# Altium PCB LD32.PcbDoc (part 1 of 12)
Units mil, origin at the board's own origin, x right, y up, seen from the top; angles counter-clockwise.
Board outline 7007.87 x 4368.85 mil, 12 copper layers (Top Layer, Int1 (GND), Int2 (AVDD), Int3 (DVDD), Int4 (GND), Int5 (ST), Int6 (SB), Int8 (AGND), Int7 (AVCC), Int9 (VCCA), Int10 (GND), Bottom Layer), stack 60.136 mil thick; 1165 components, 667 nets, 3910 pads, 2570 vias.
Unrouted connection lines stored in the file: 14.
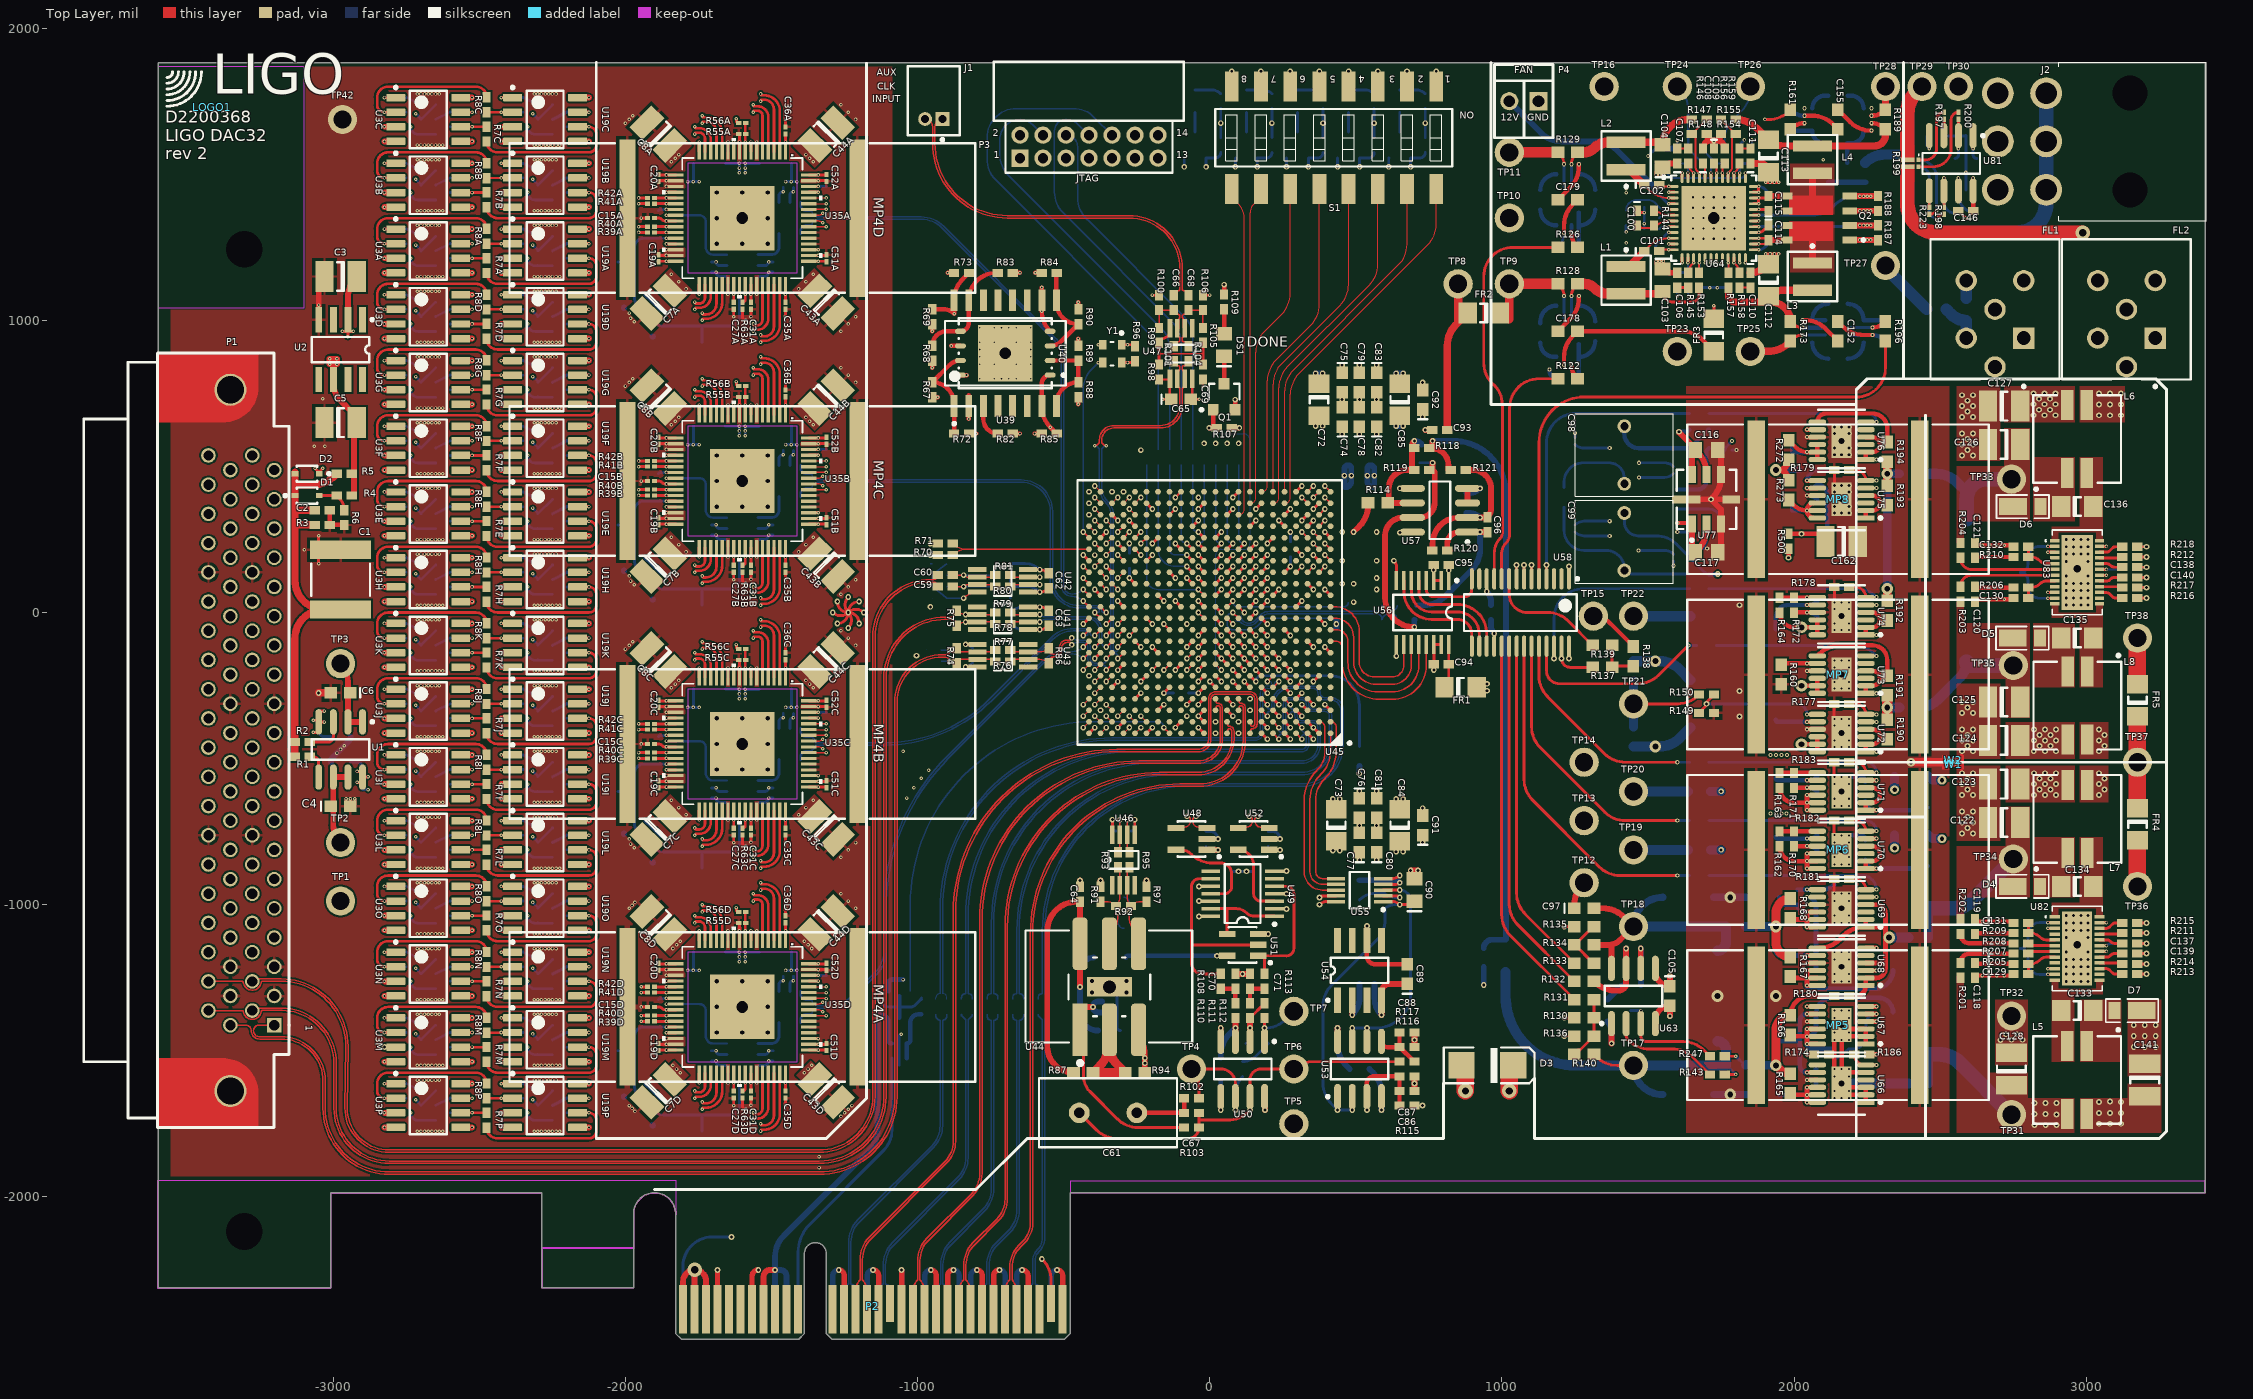
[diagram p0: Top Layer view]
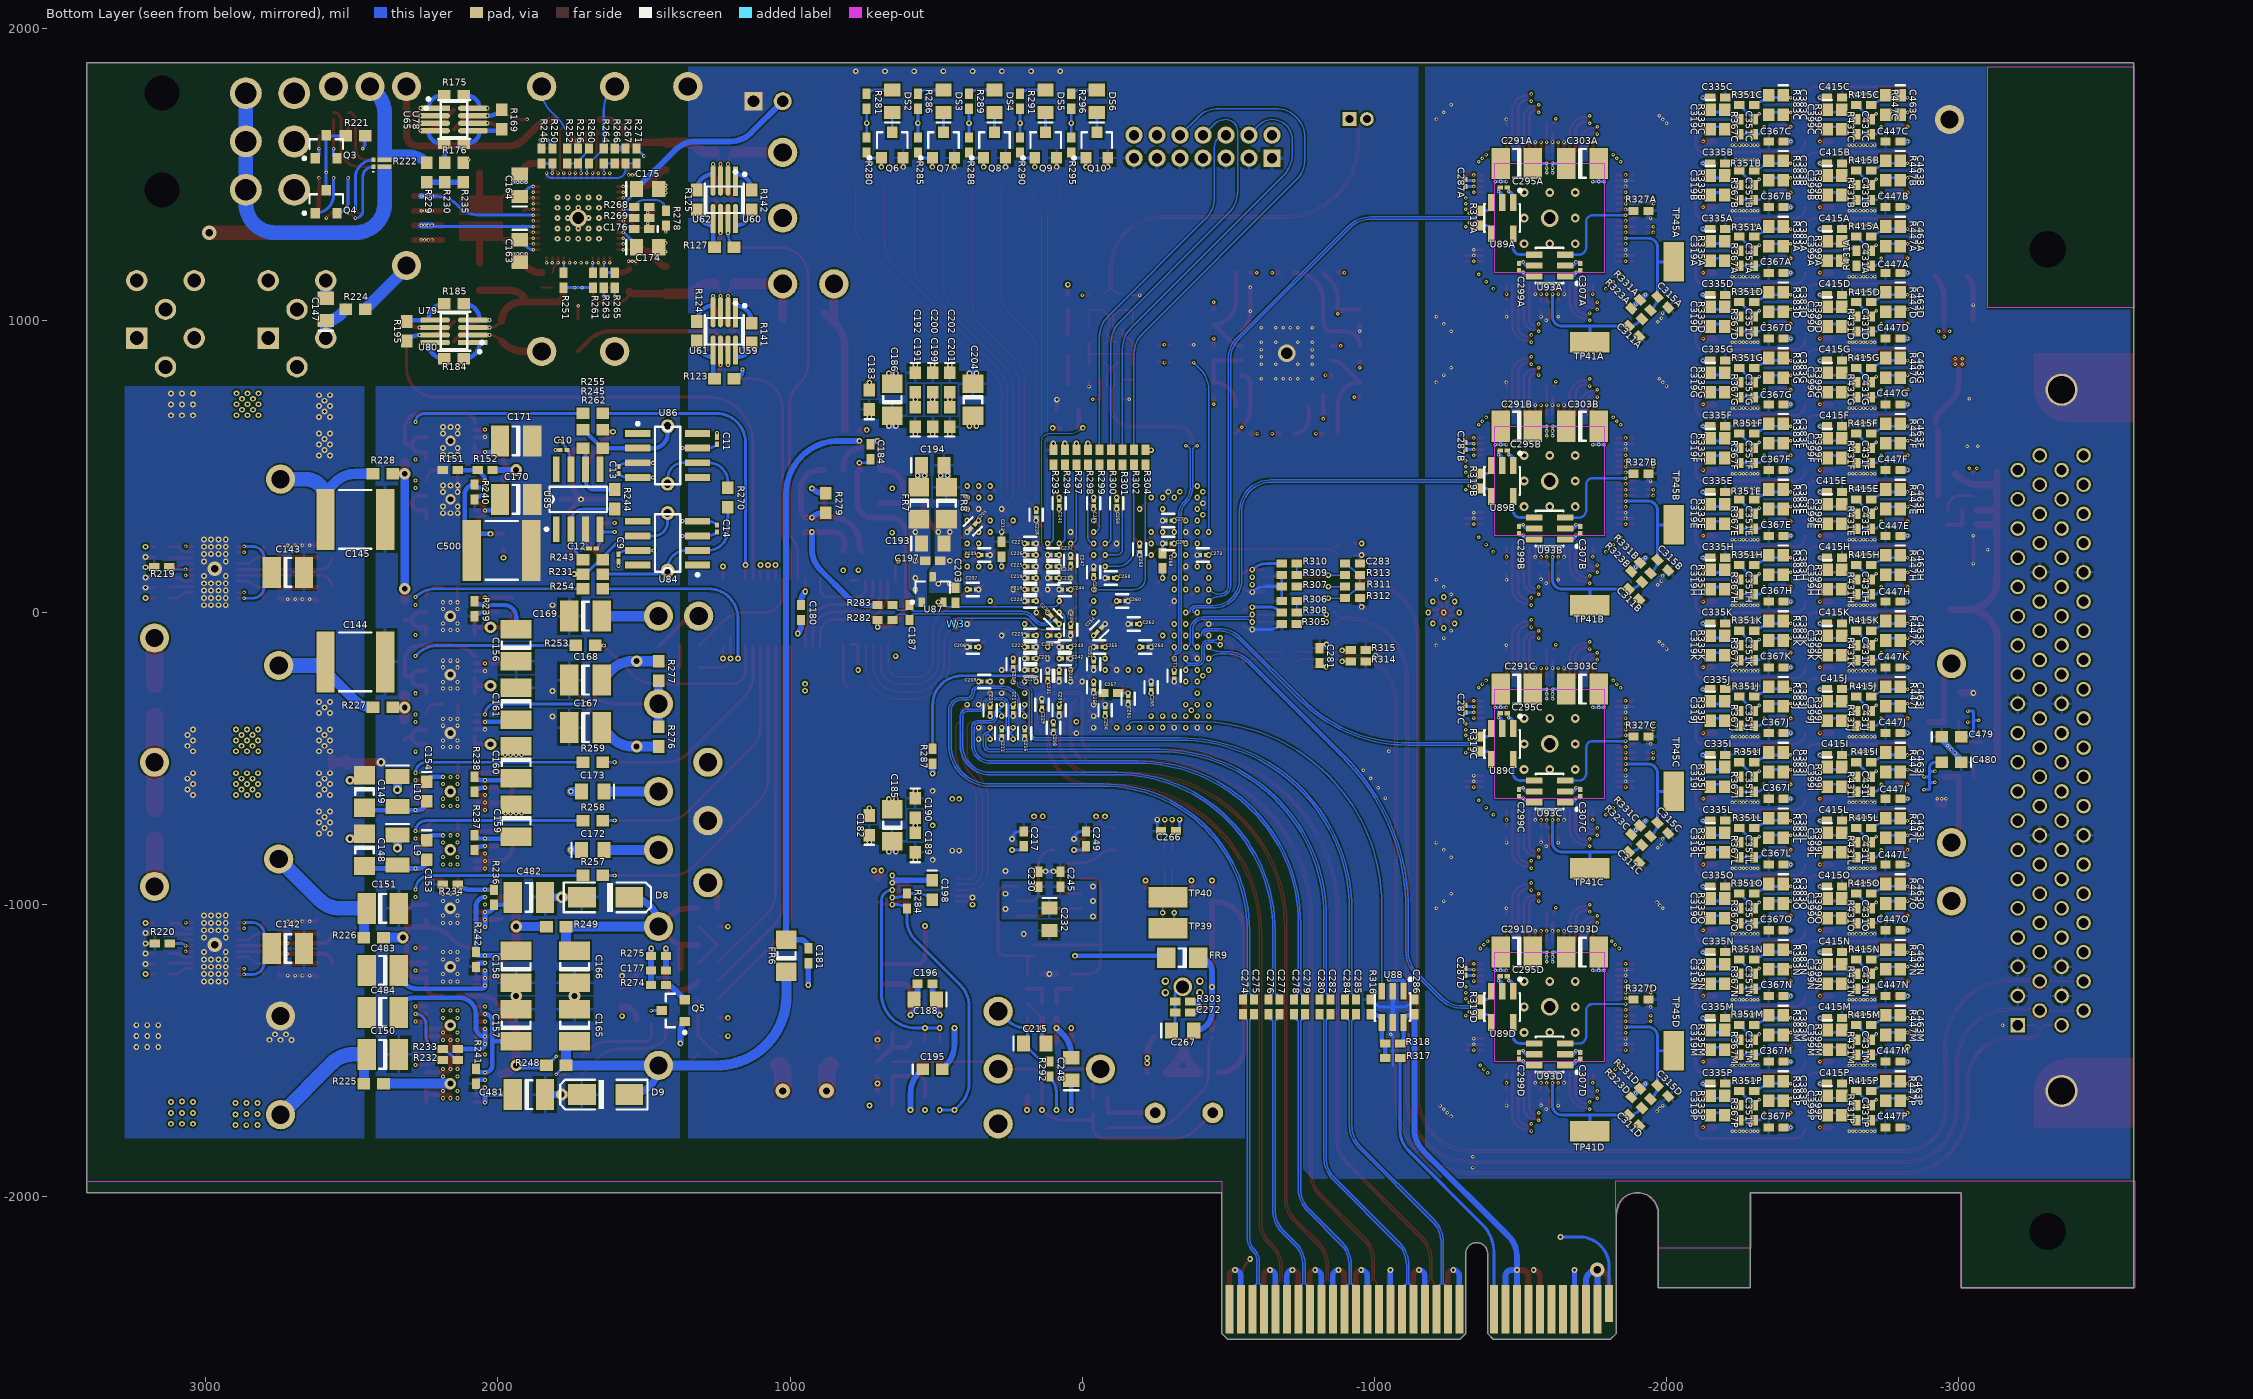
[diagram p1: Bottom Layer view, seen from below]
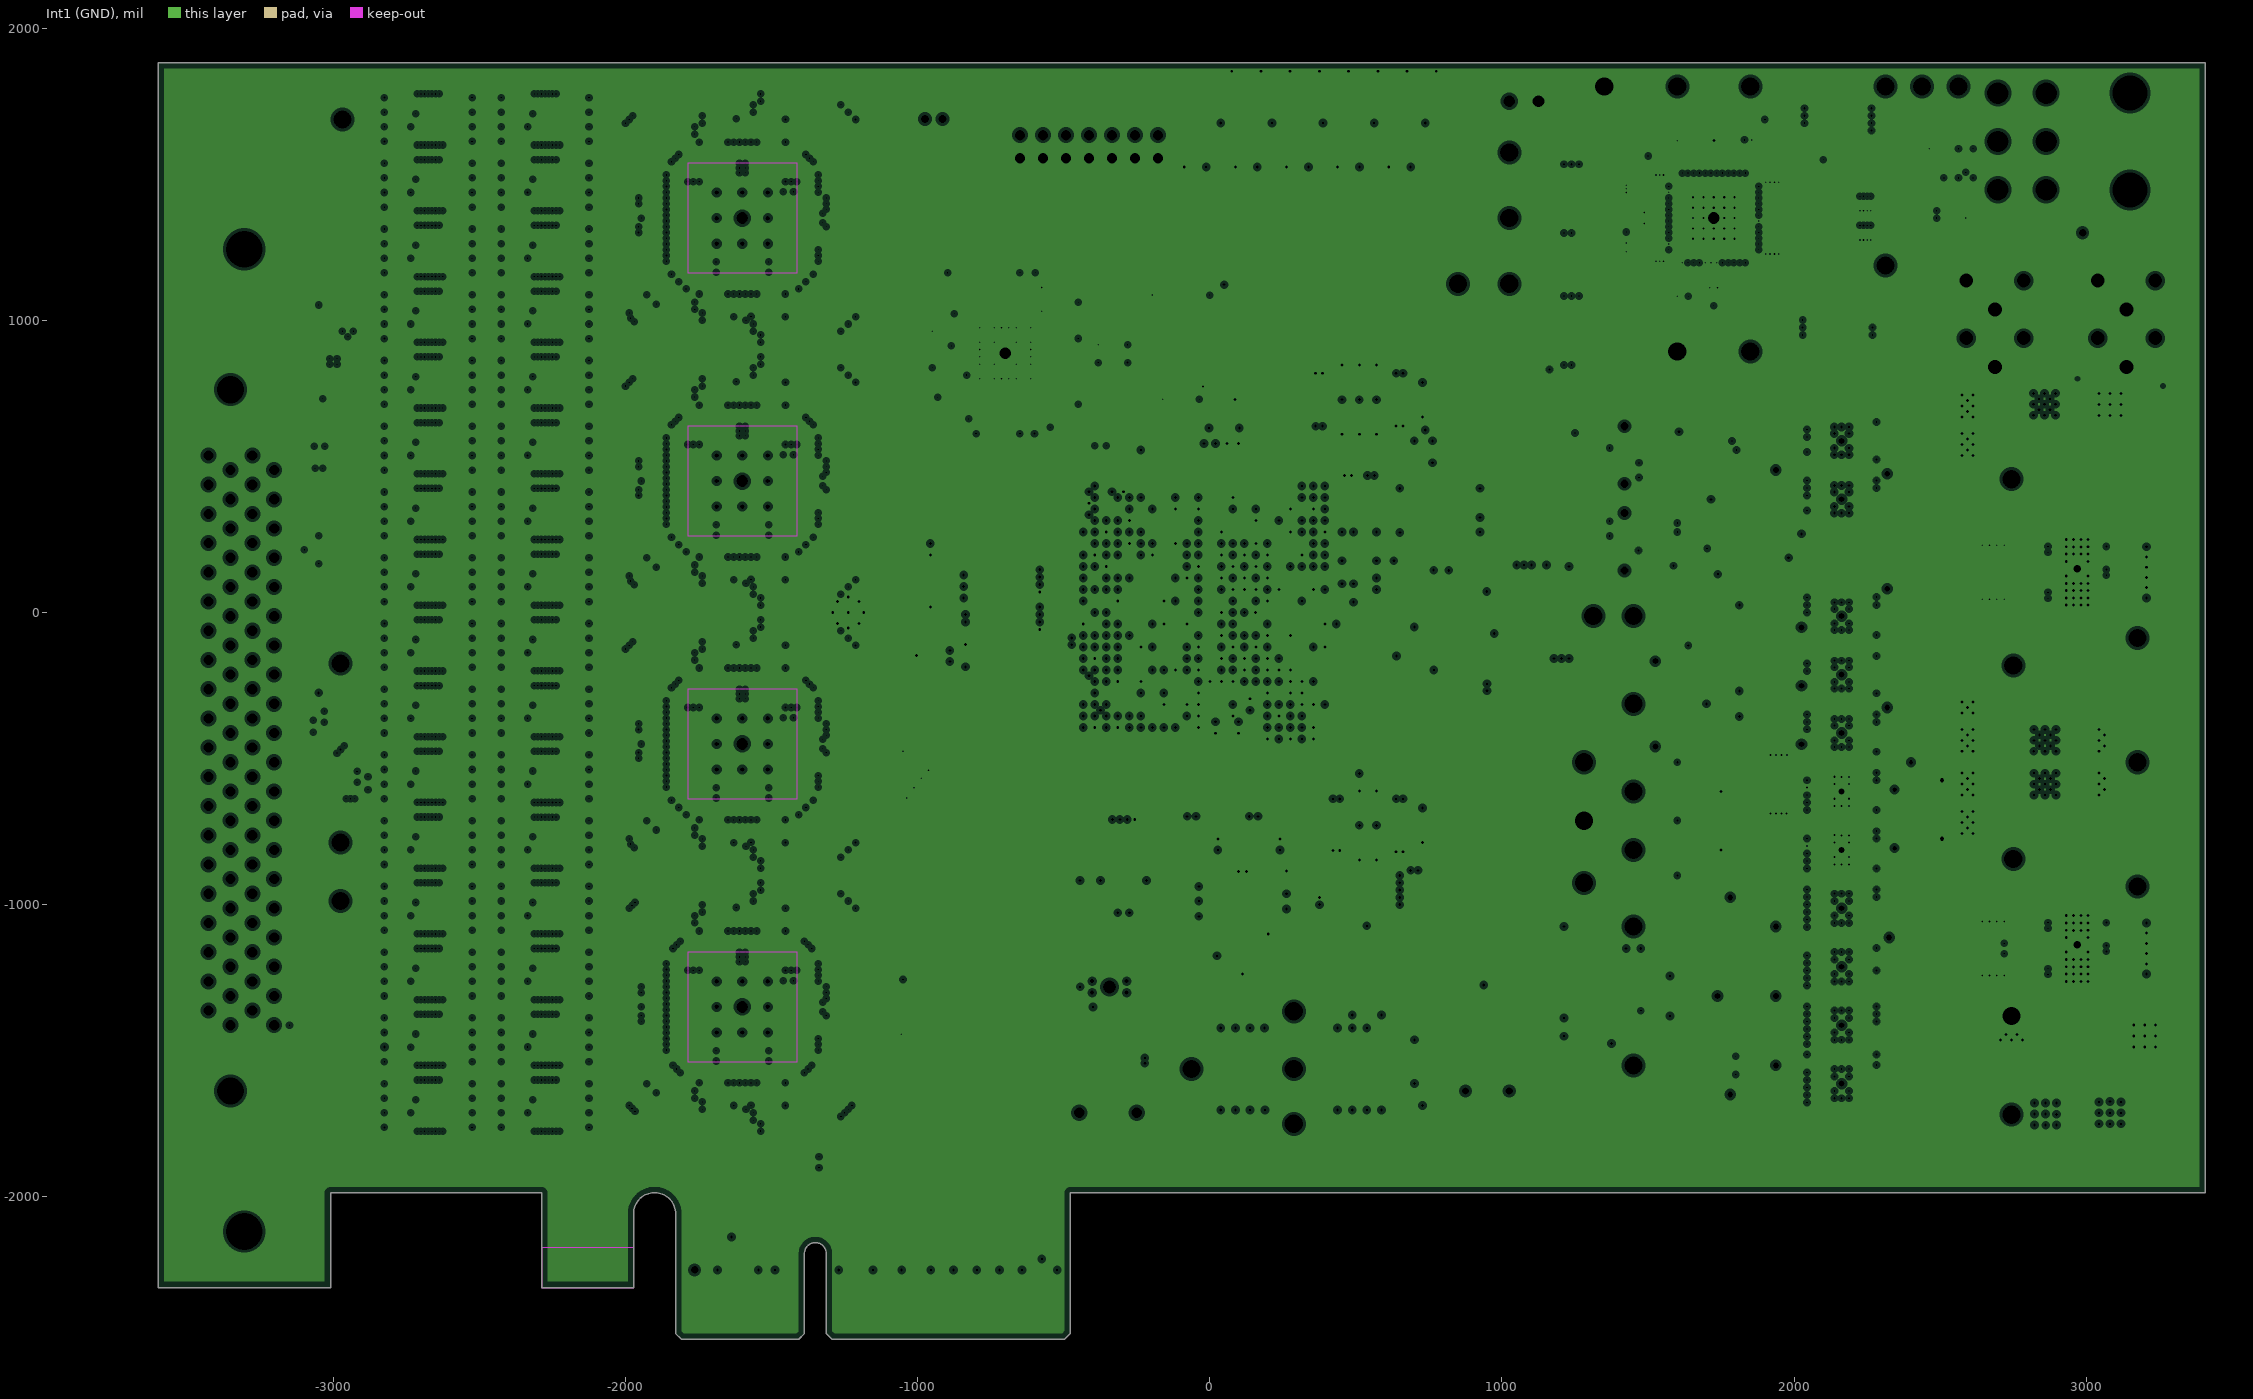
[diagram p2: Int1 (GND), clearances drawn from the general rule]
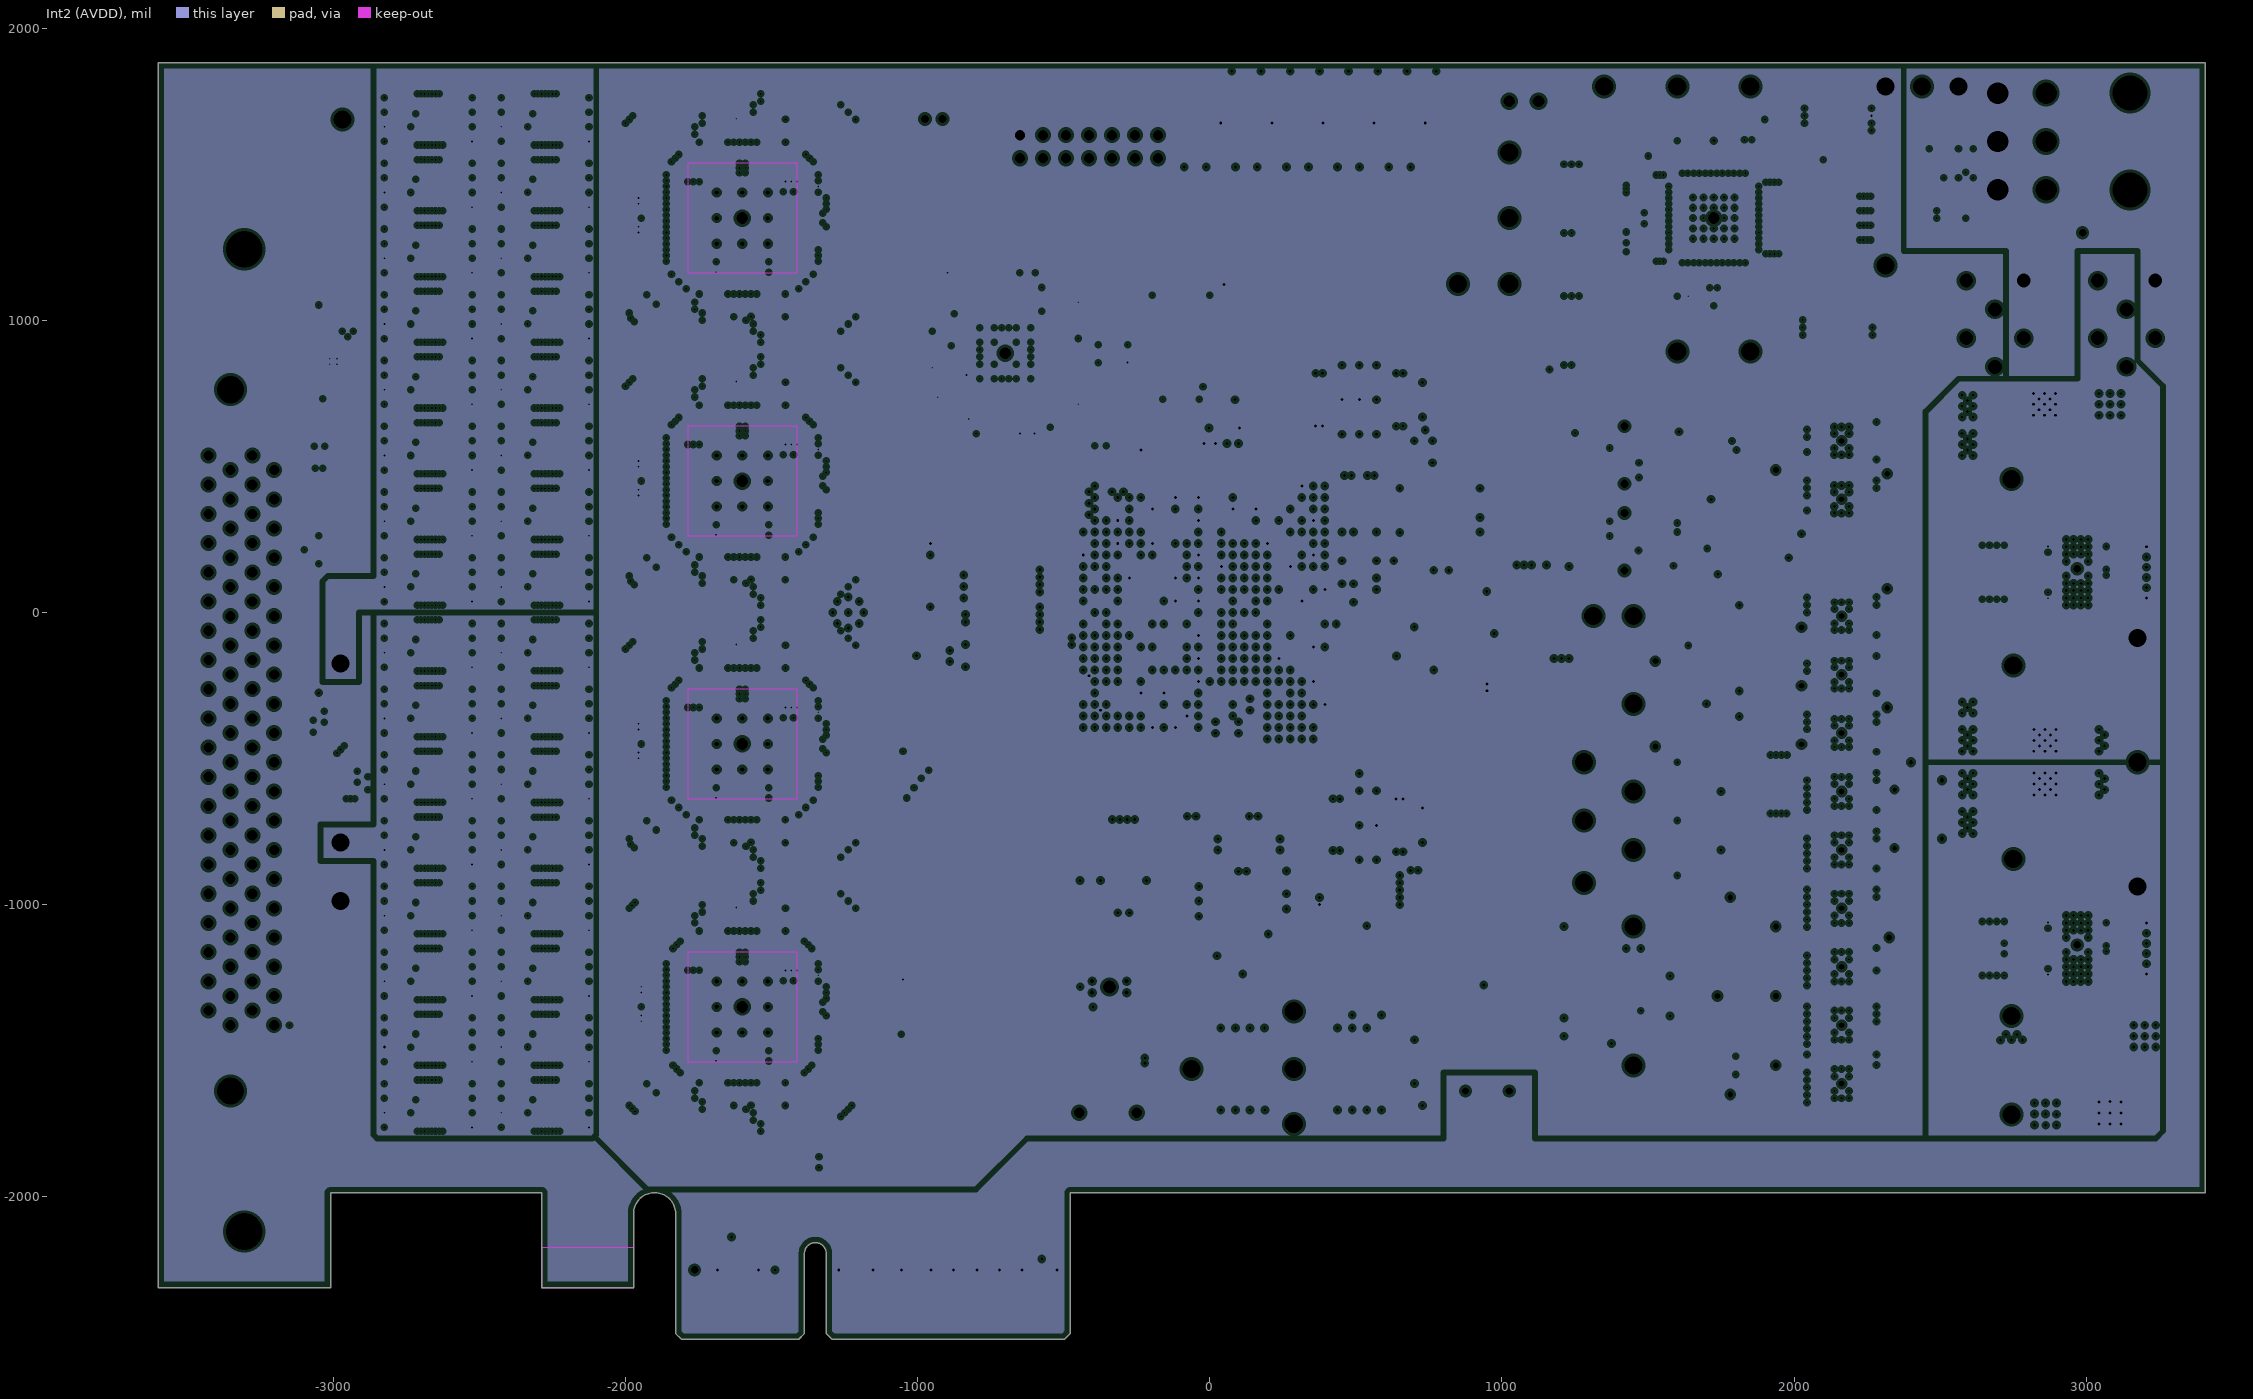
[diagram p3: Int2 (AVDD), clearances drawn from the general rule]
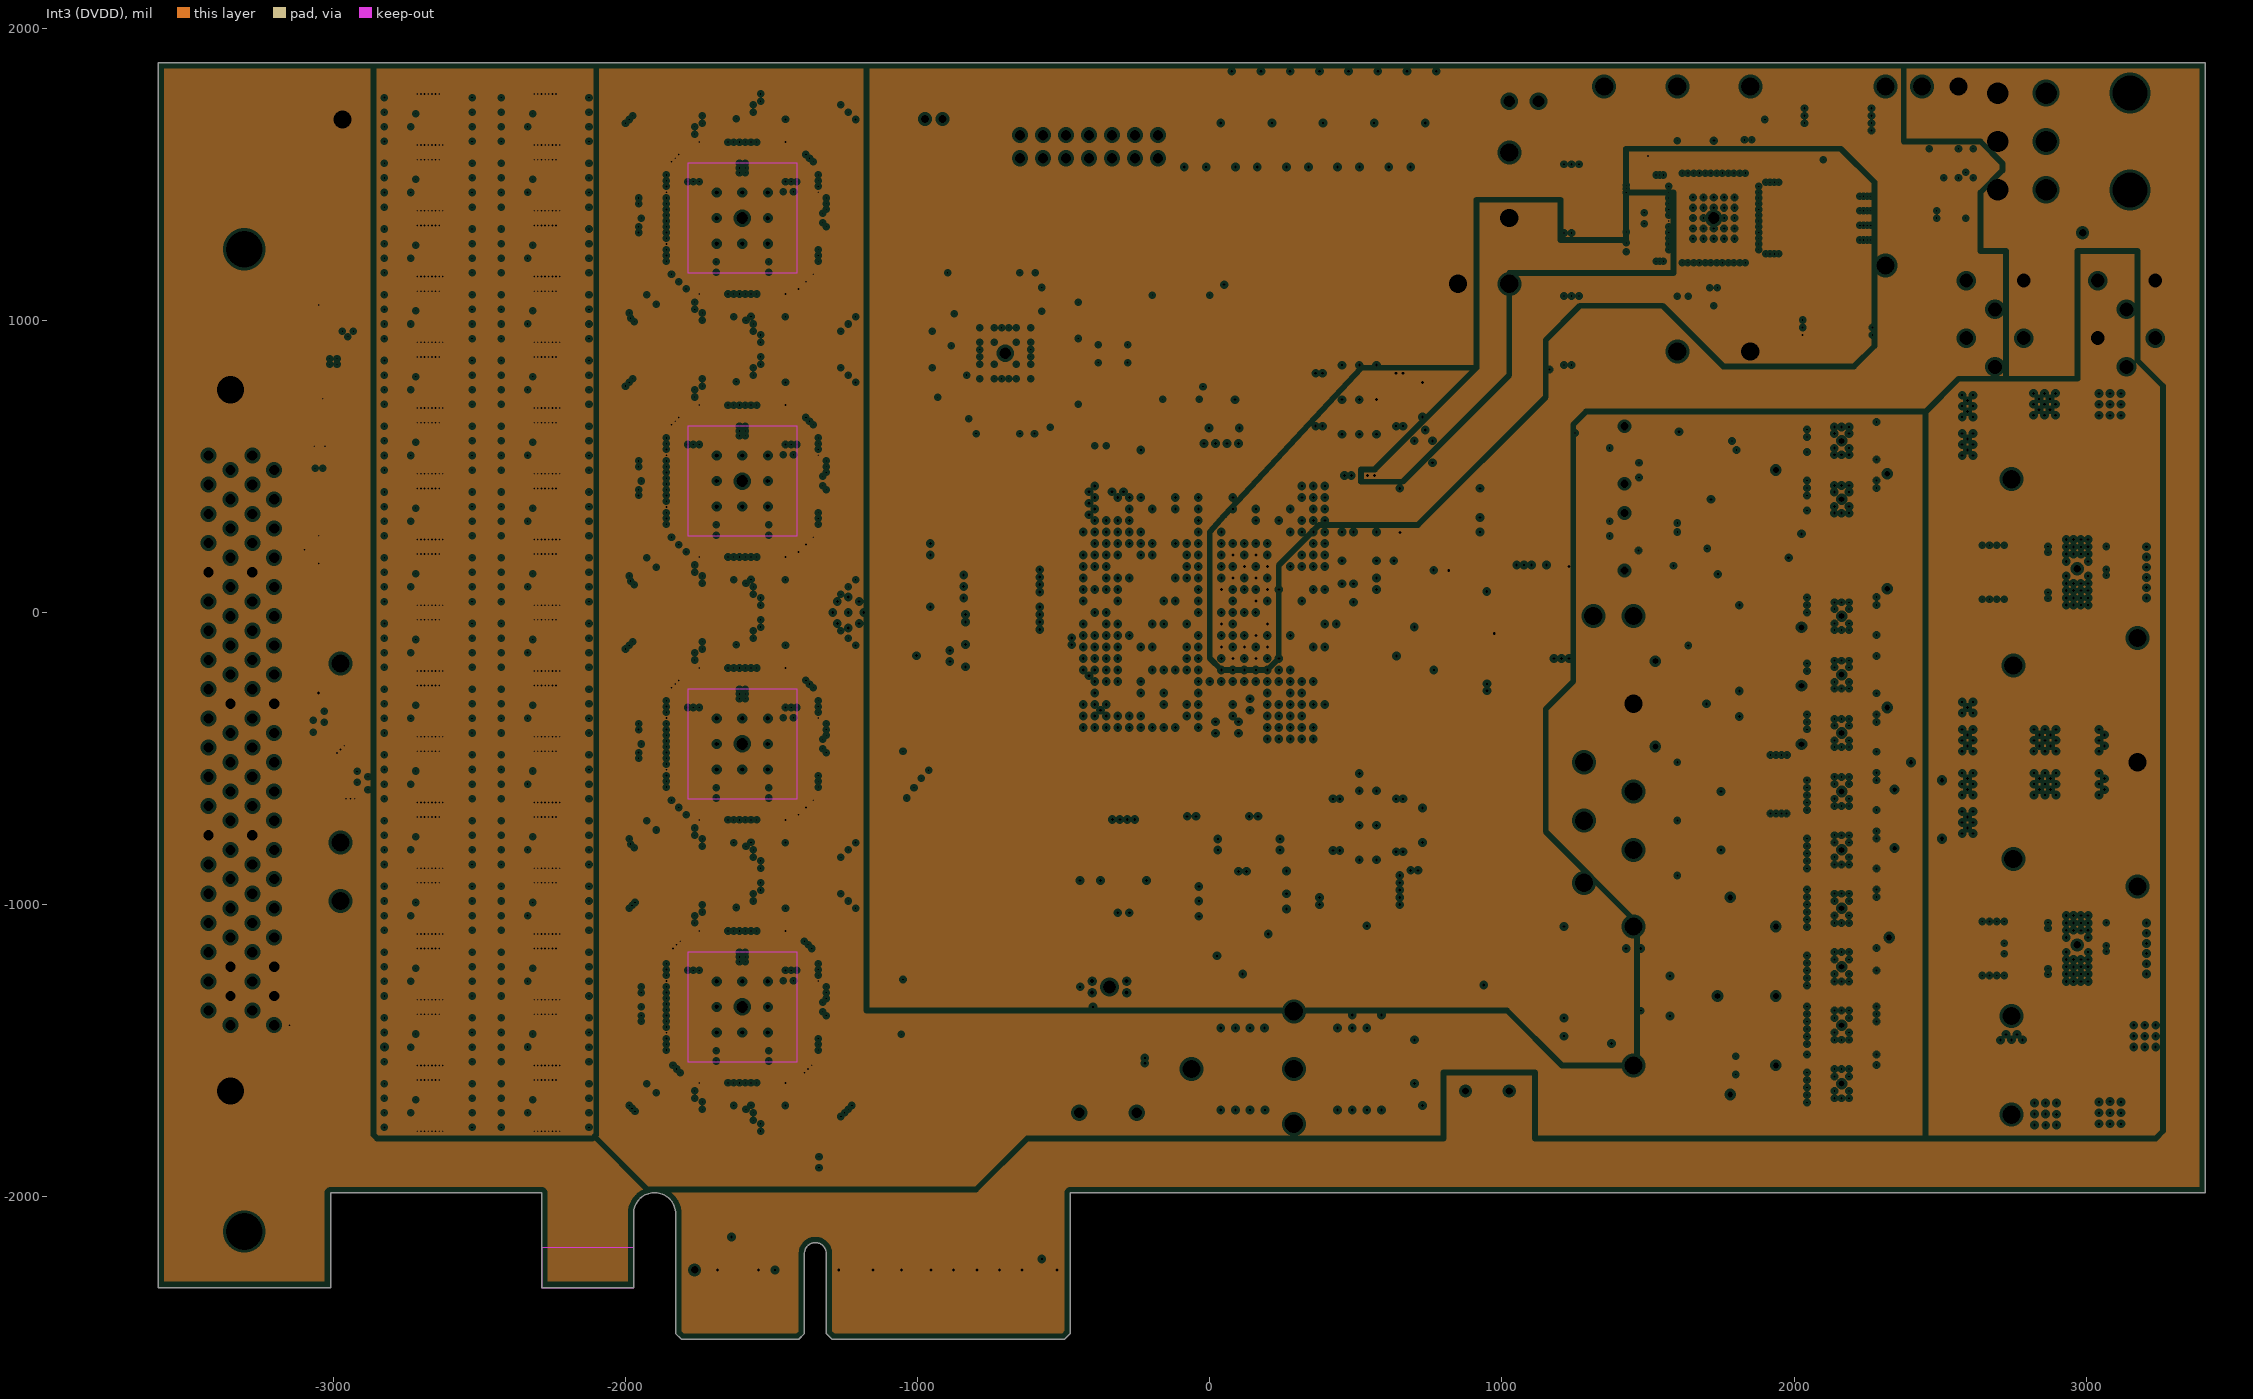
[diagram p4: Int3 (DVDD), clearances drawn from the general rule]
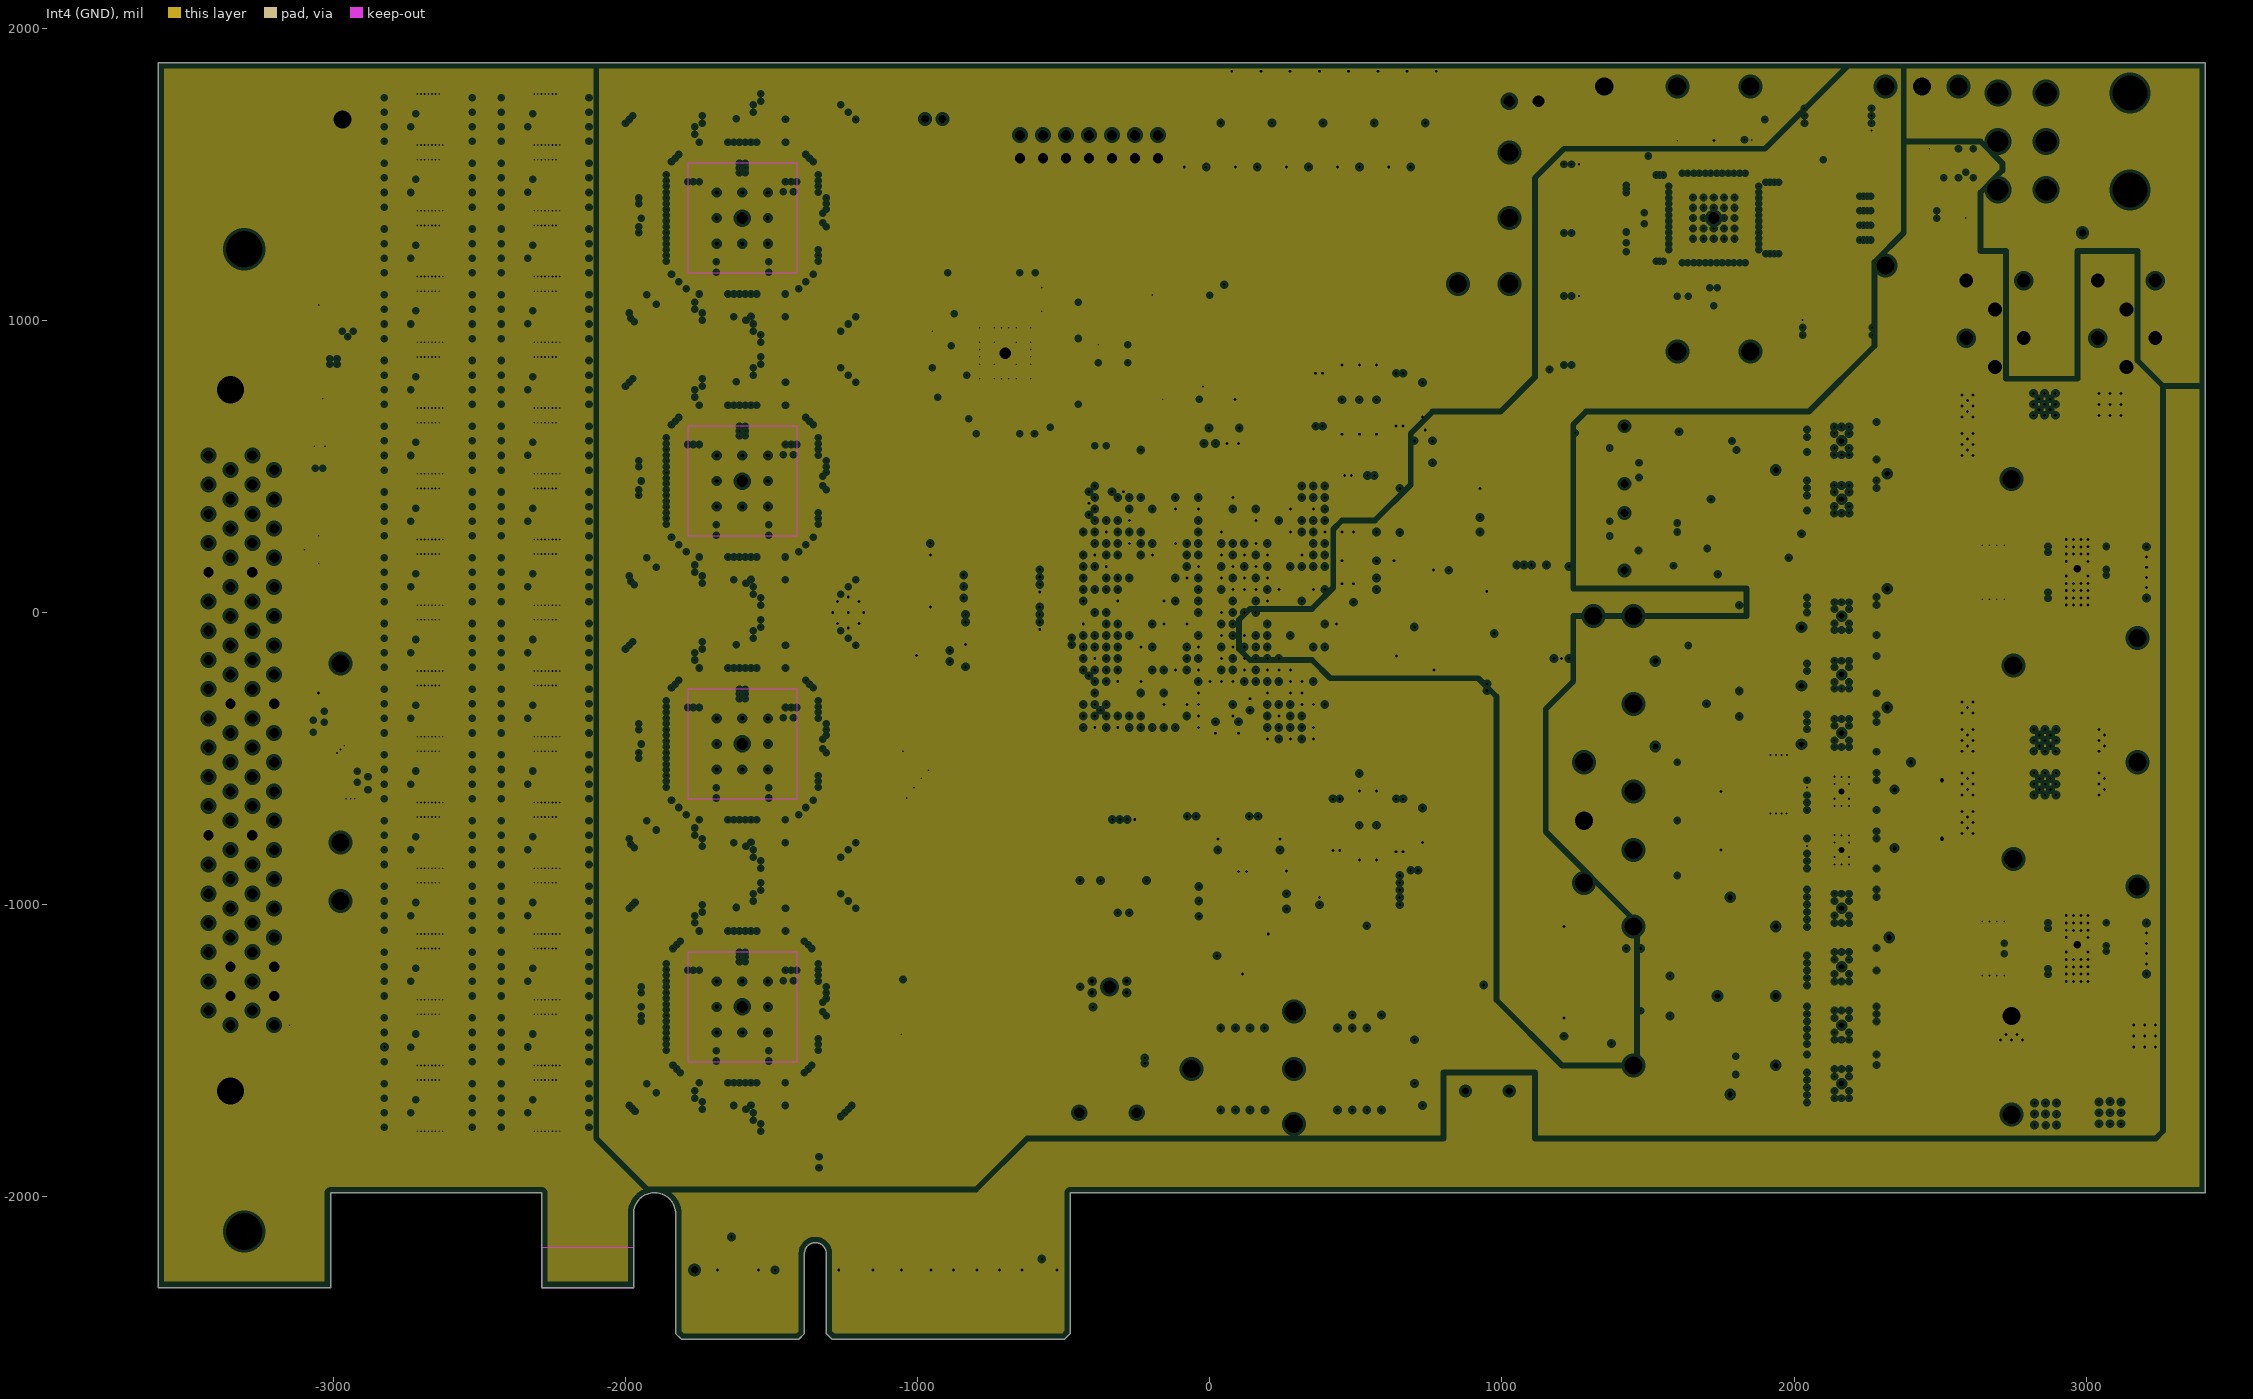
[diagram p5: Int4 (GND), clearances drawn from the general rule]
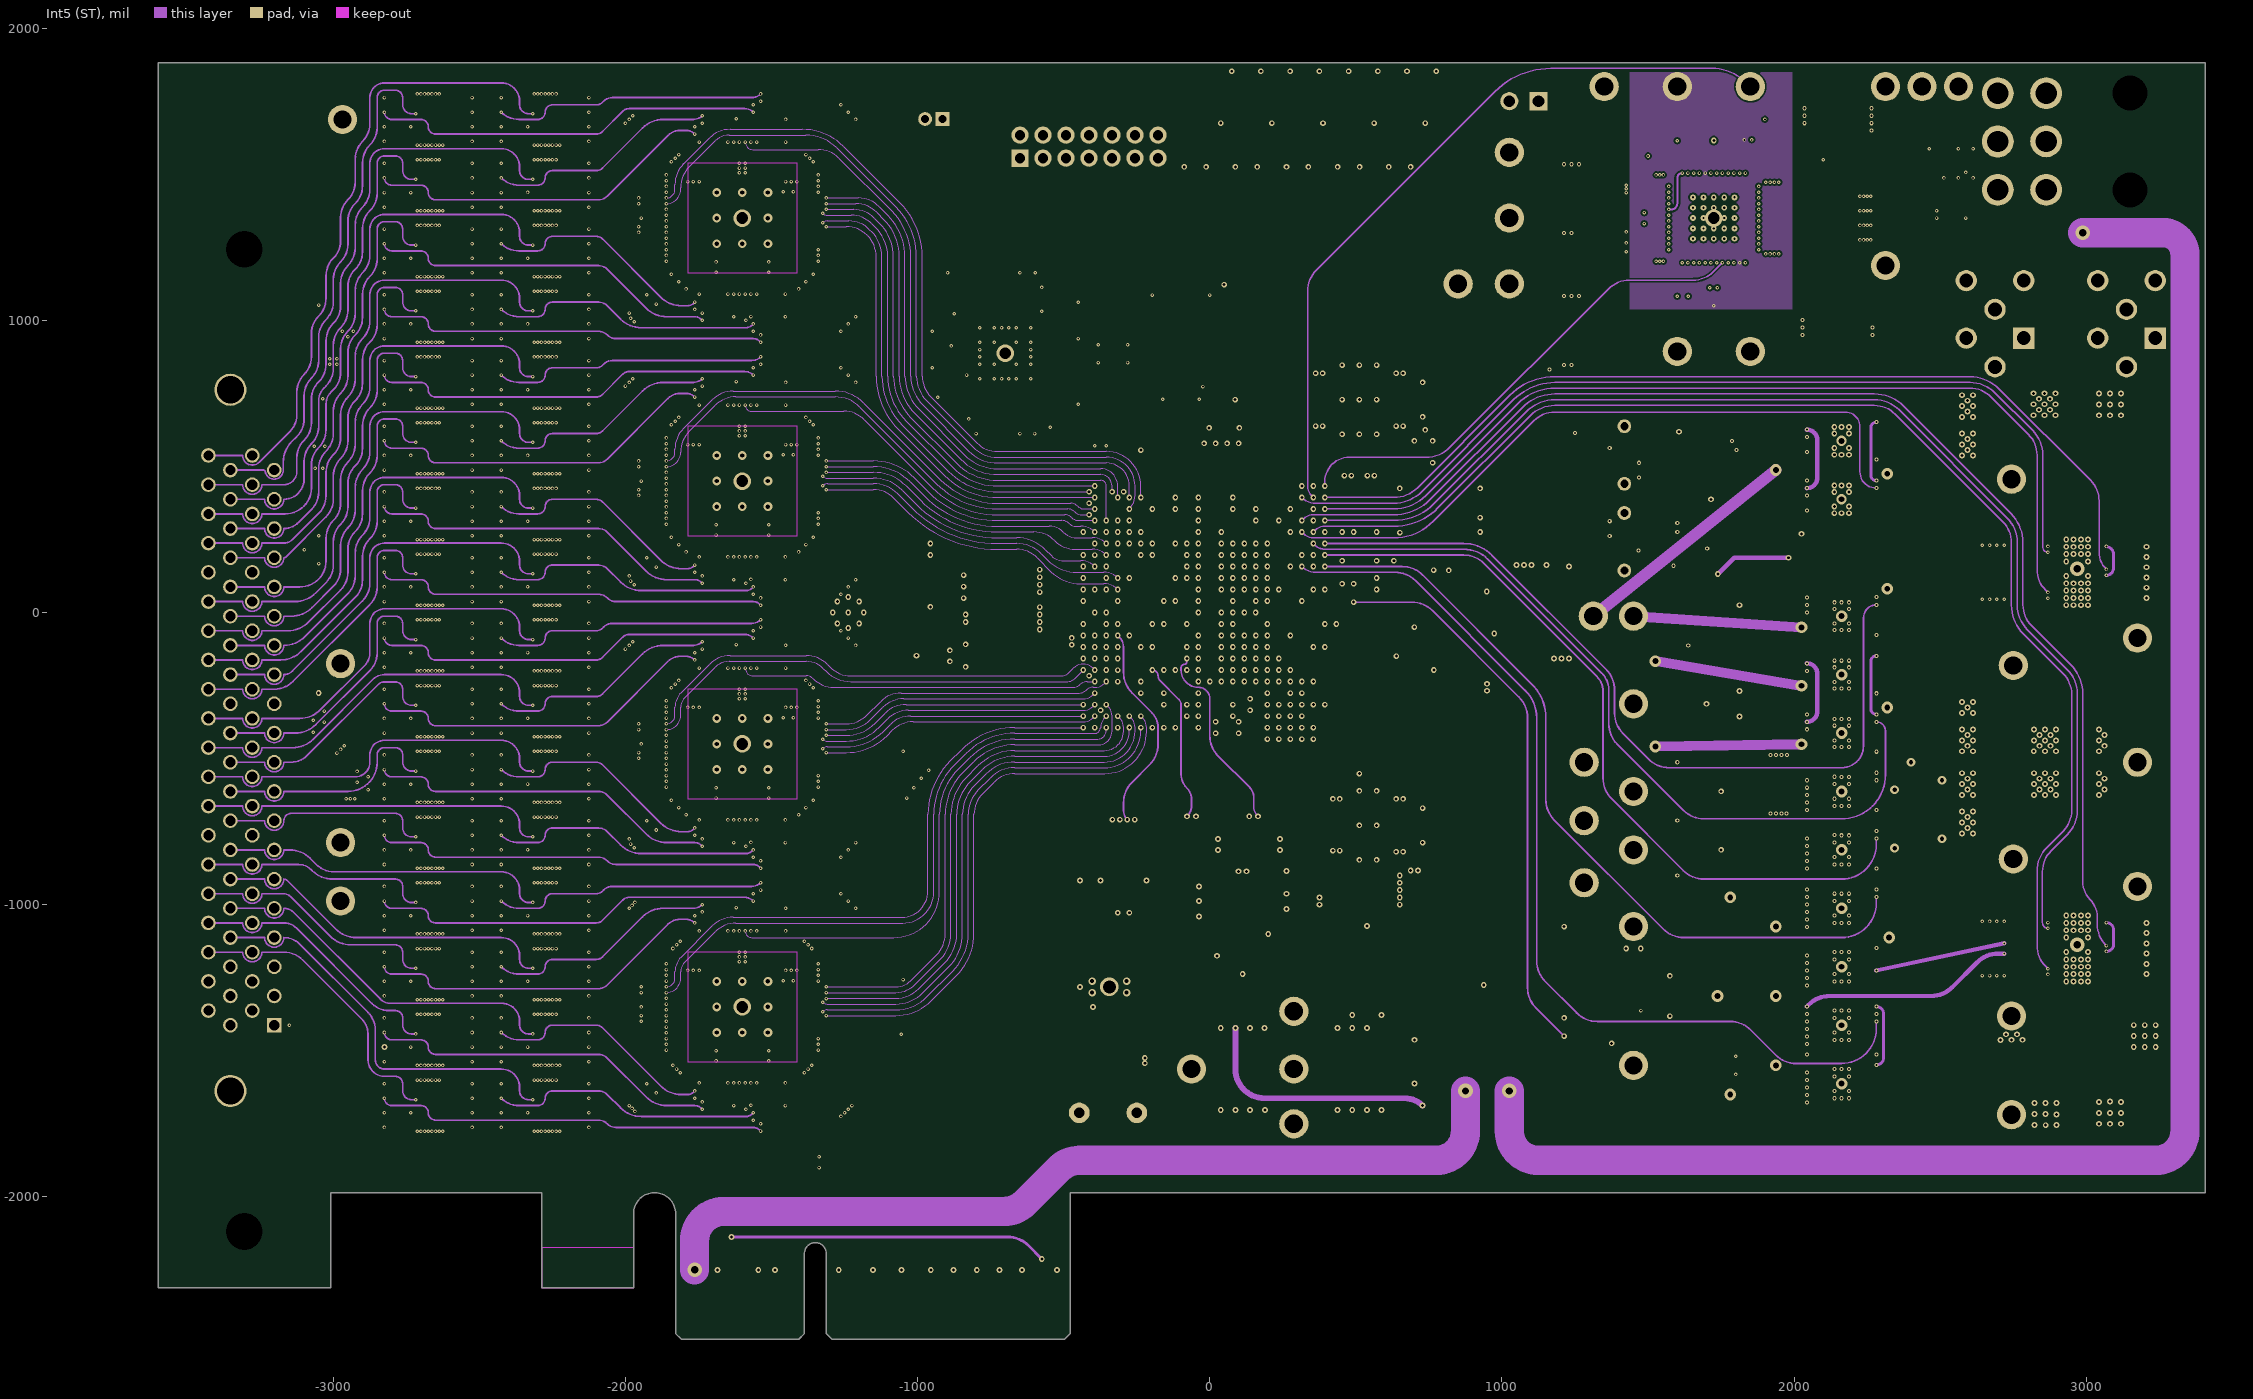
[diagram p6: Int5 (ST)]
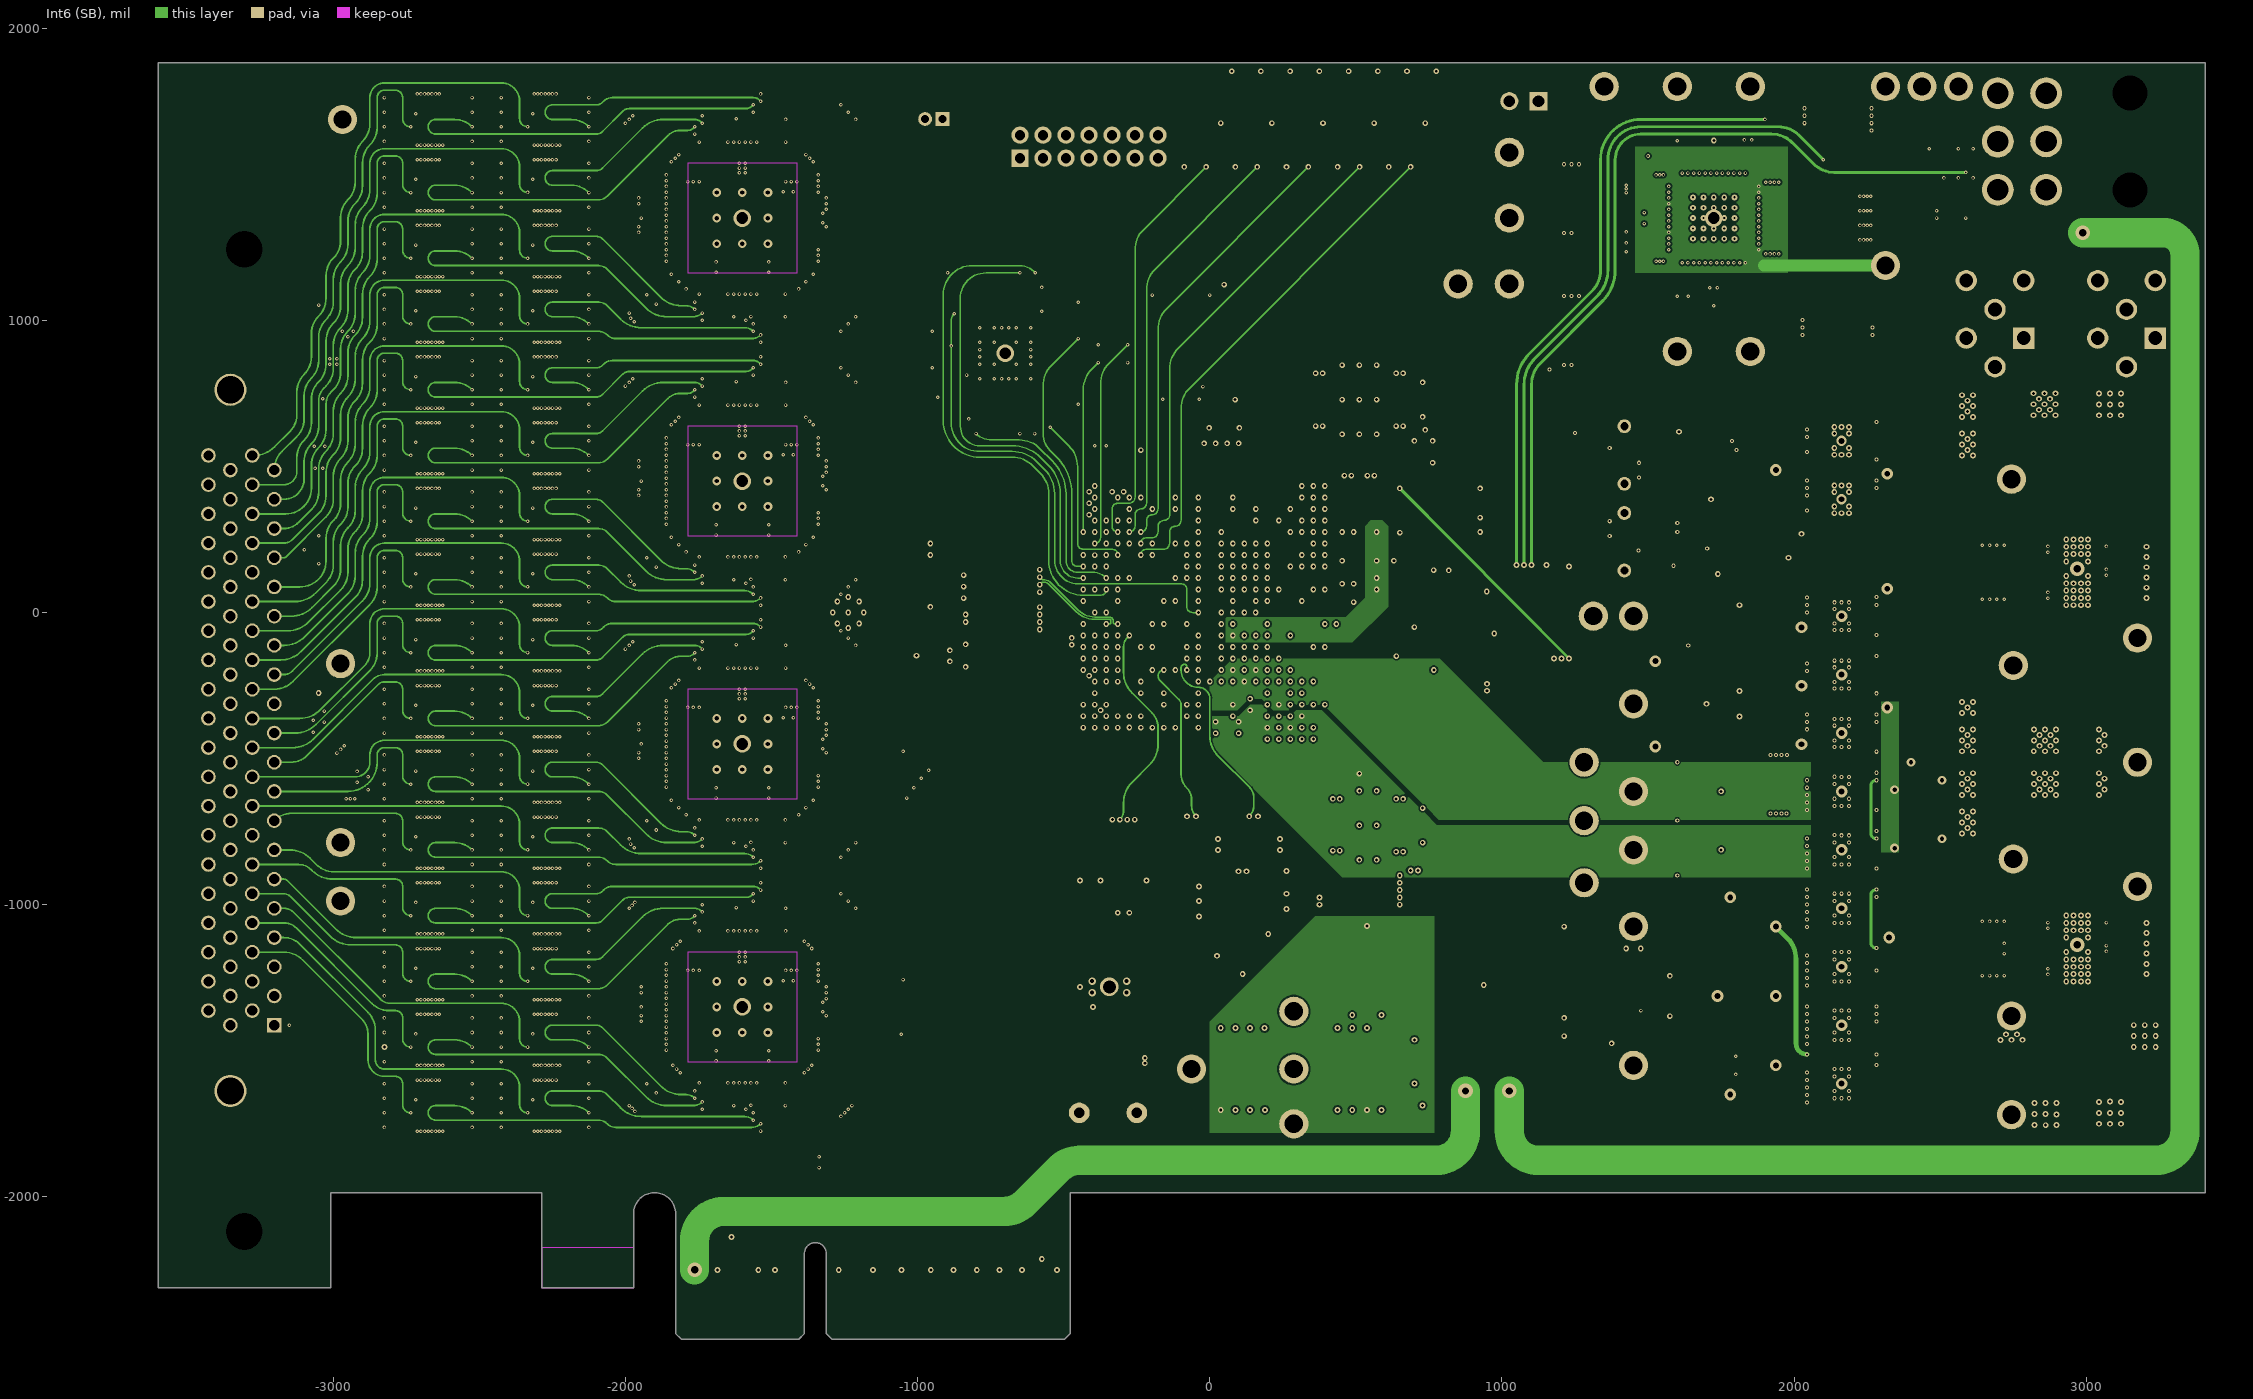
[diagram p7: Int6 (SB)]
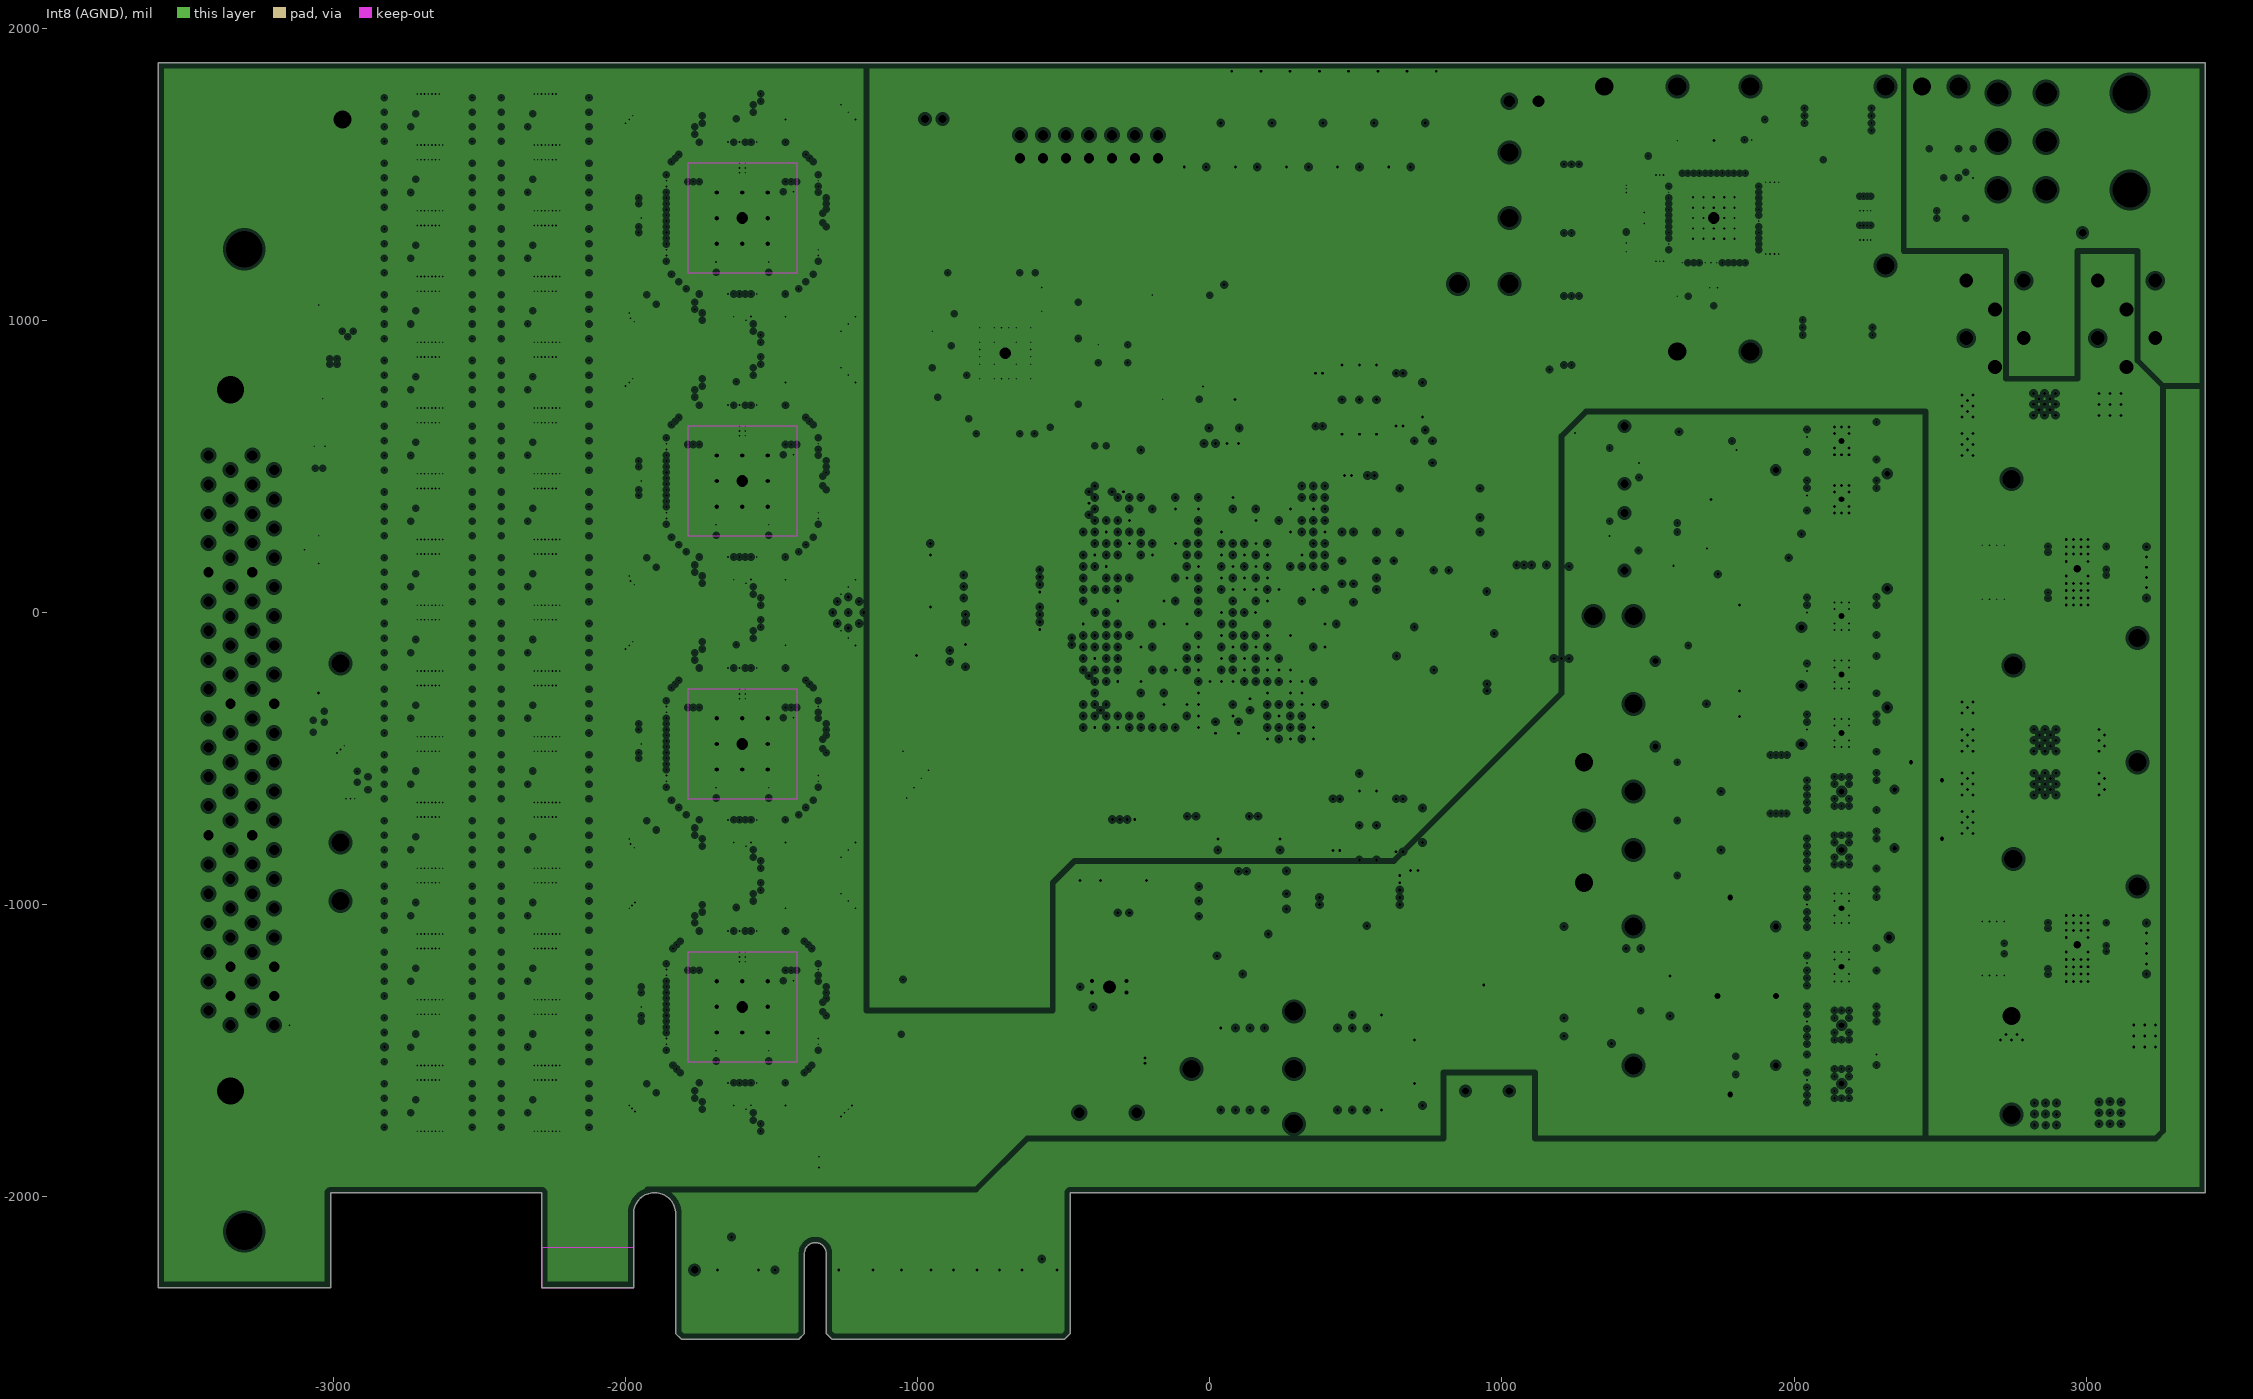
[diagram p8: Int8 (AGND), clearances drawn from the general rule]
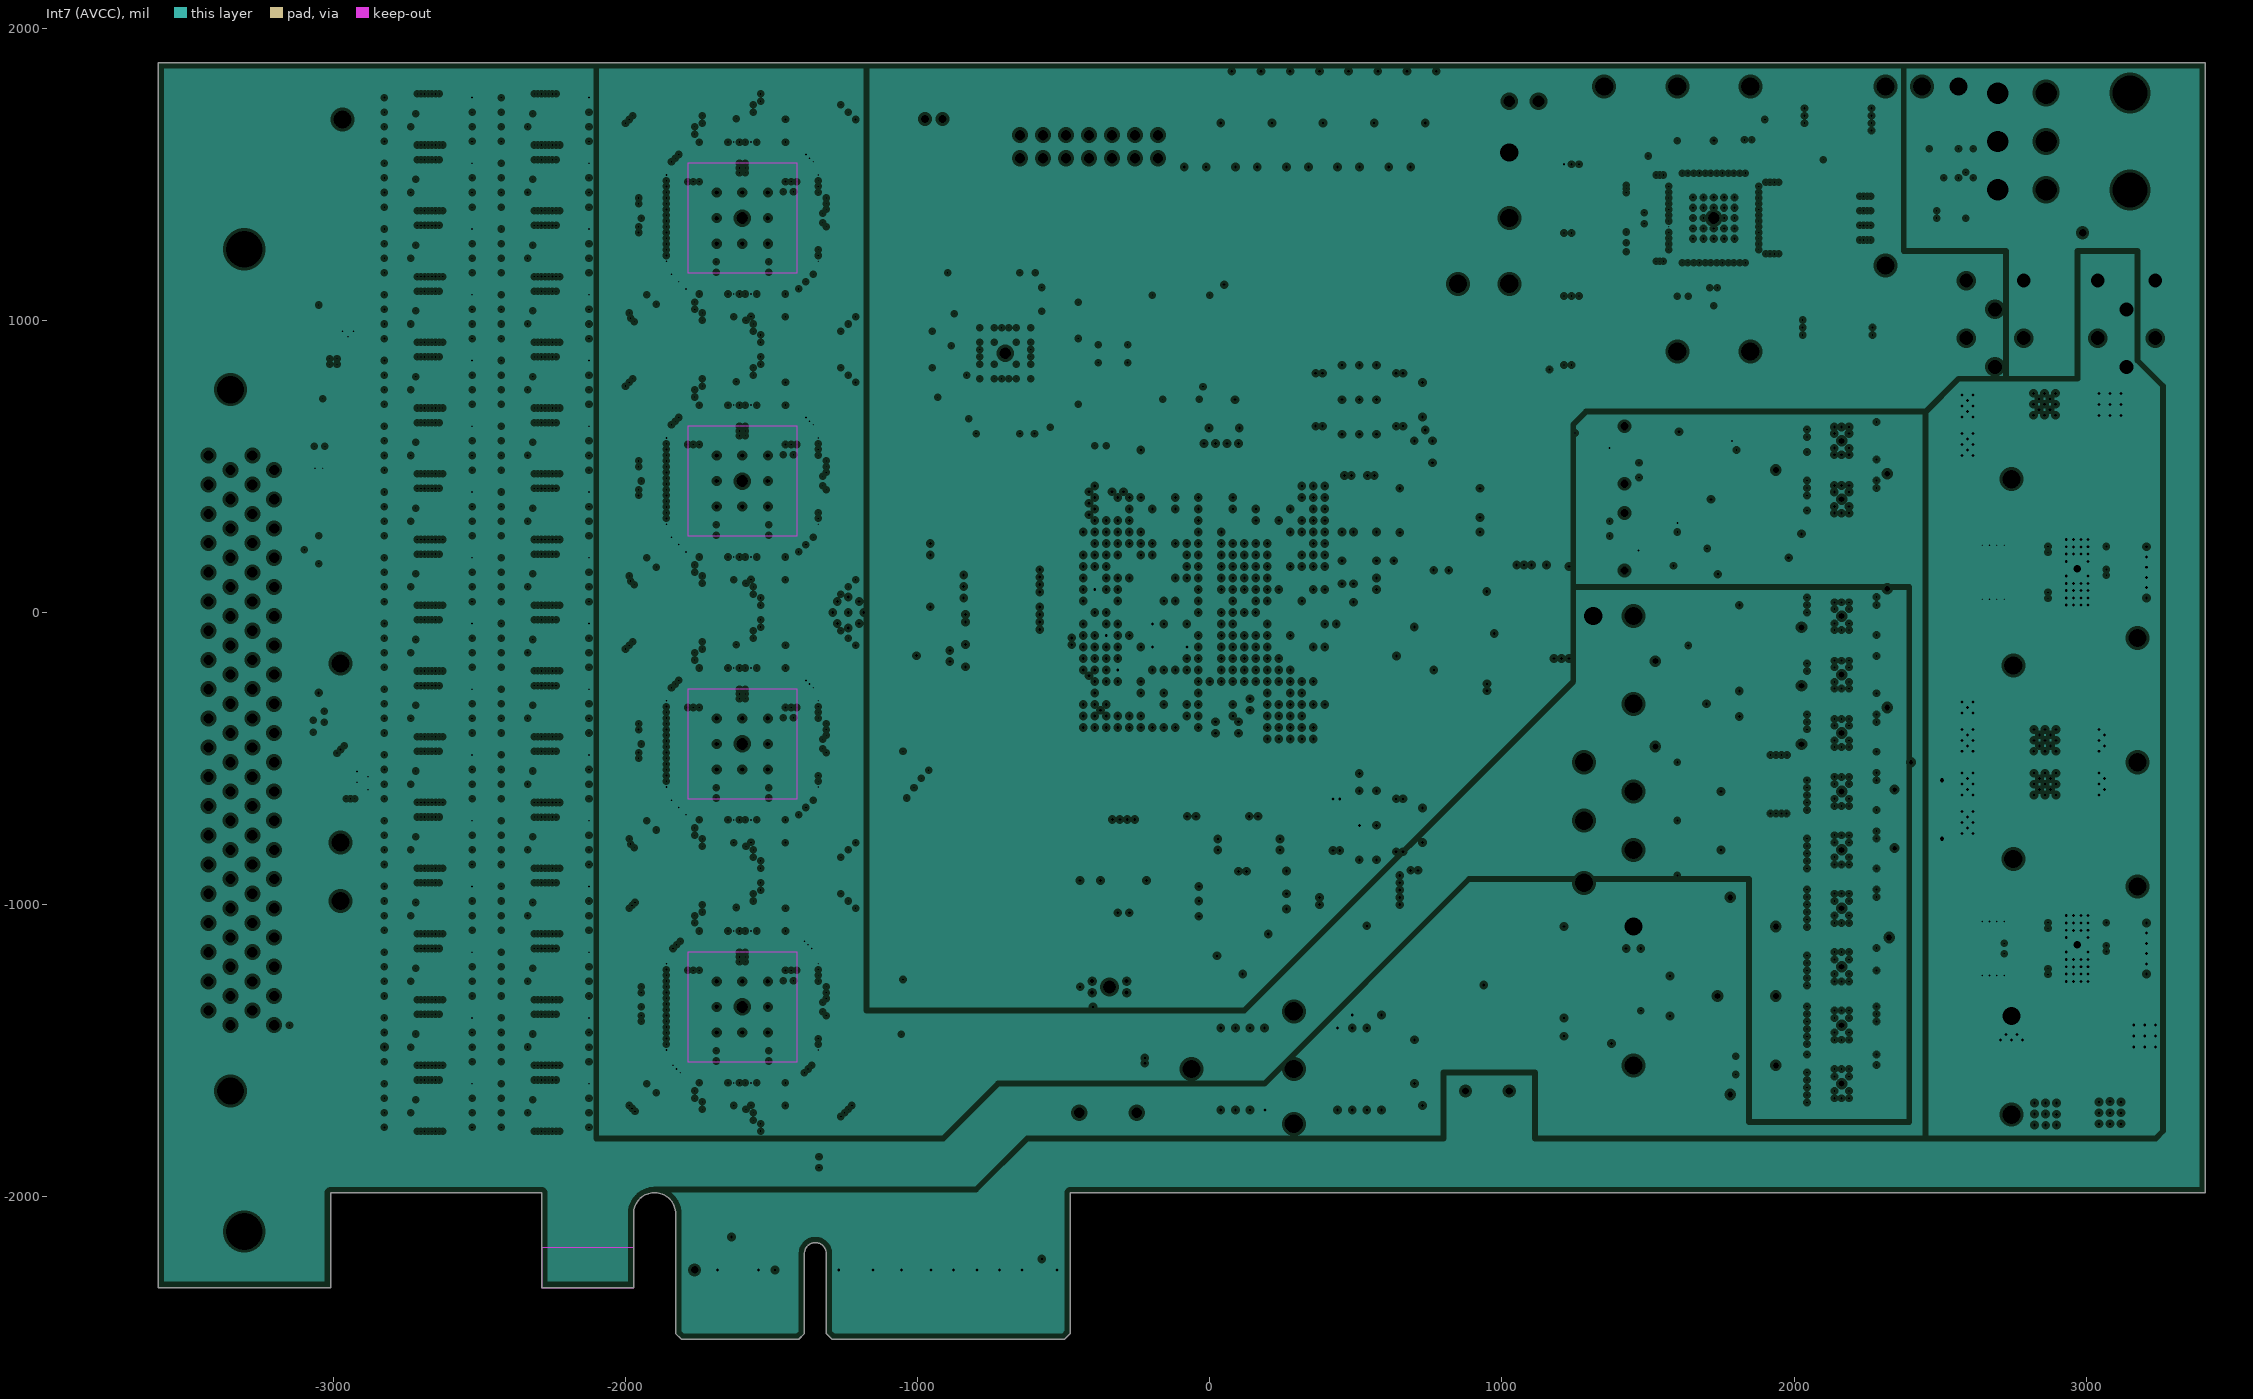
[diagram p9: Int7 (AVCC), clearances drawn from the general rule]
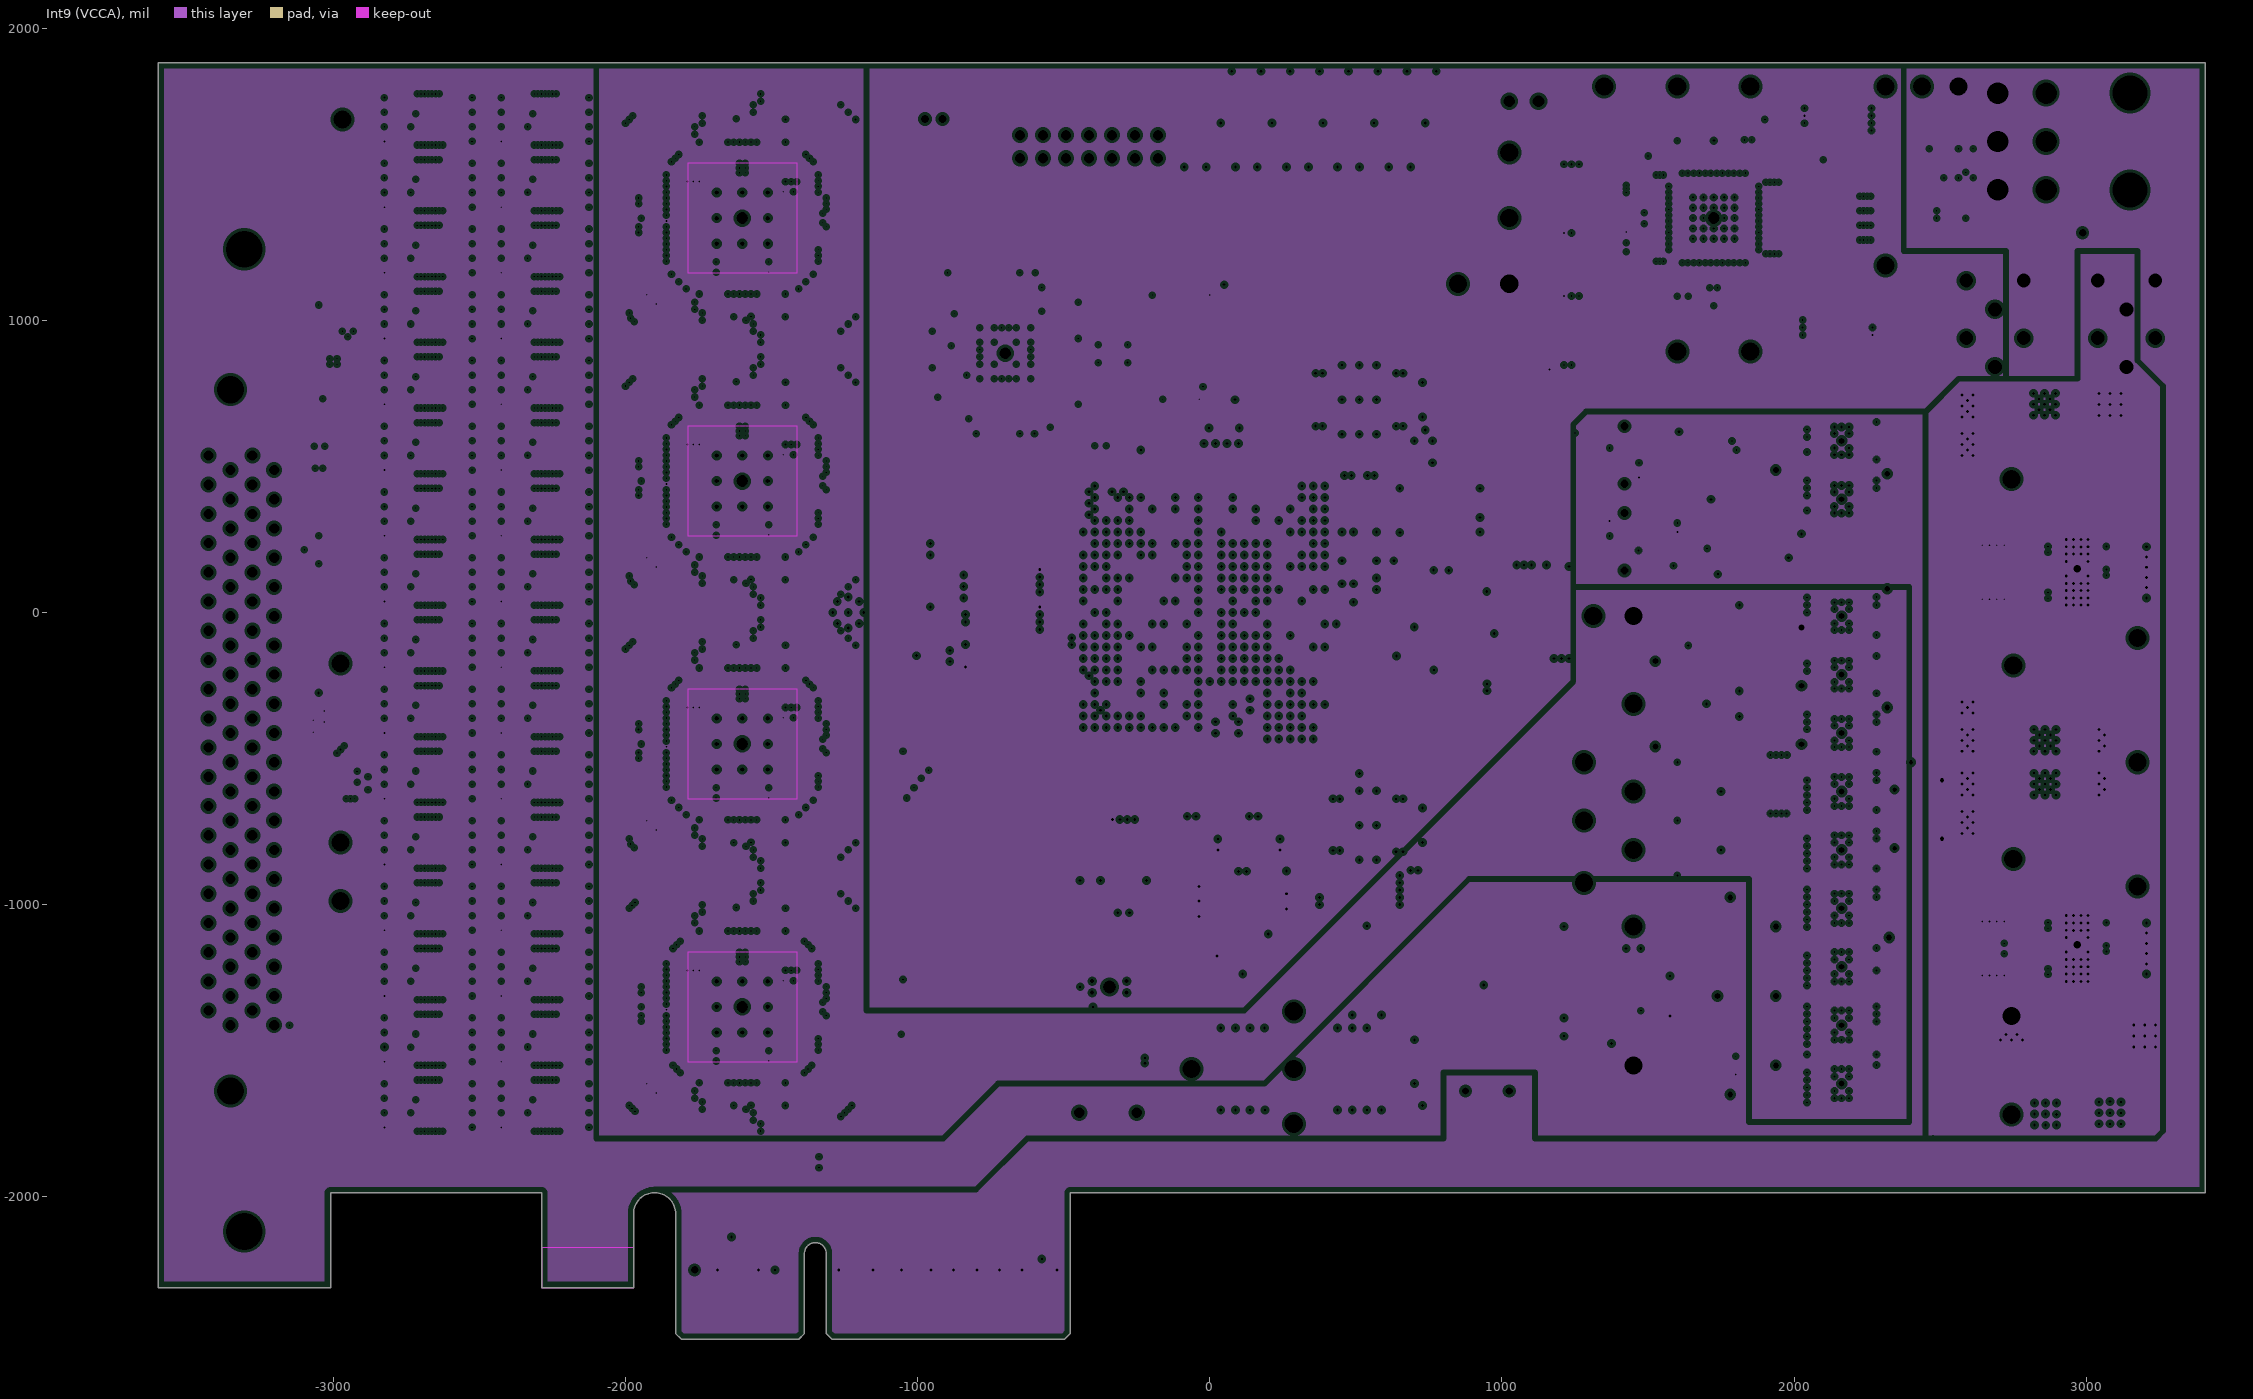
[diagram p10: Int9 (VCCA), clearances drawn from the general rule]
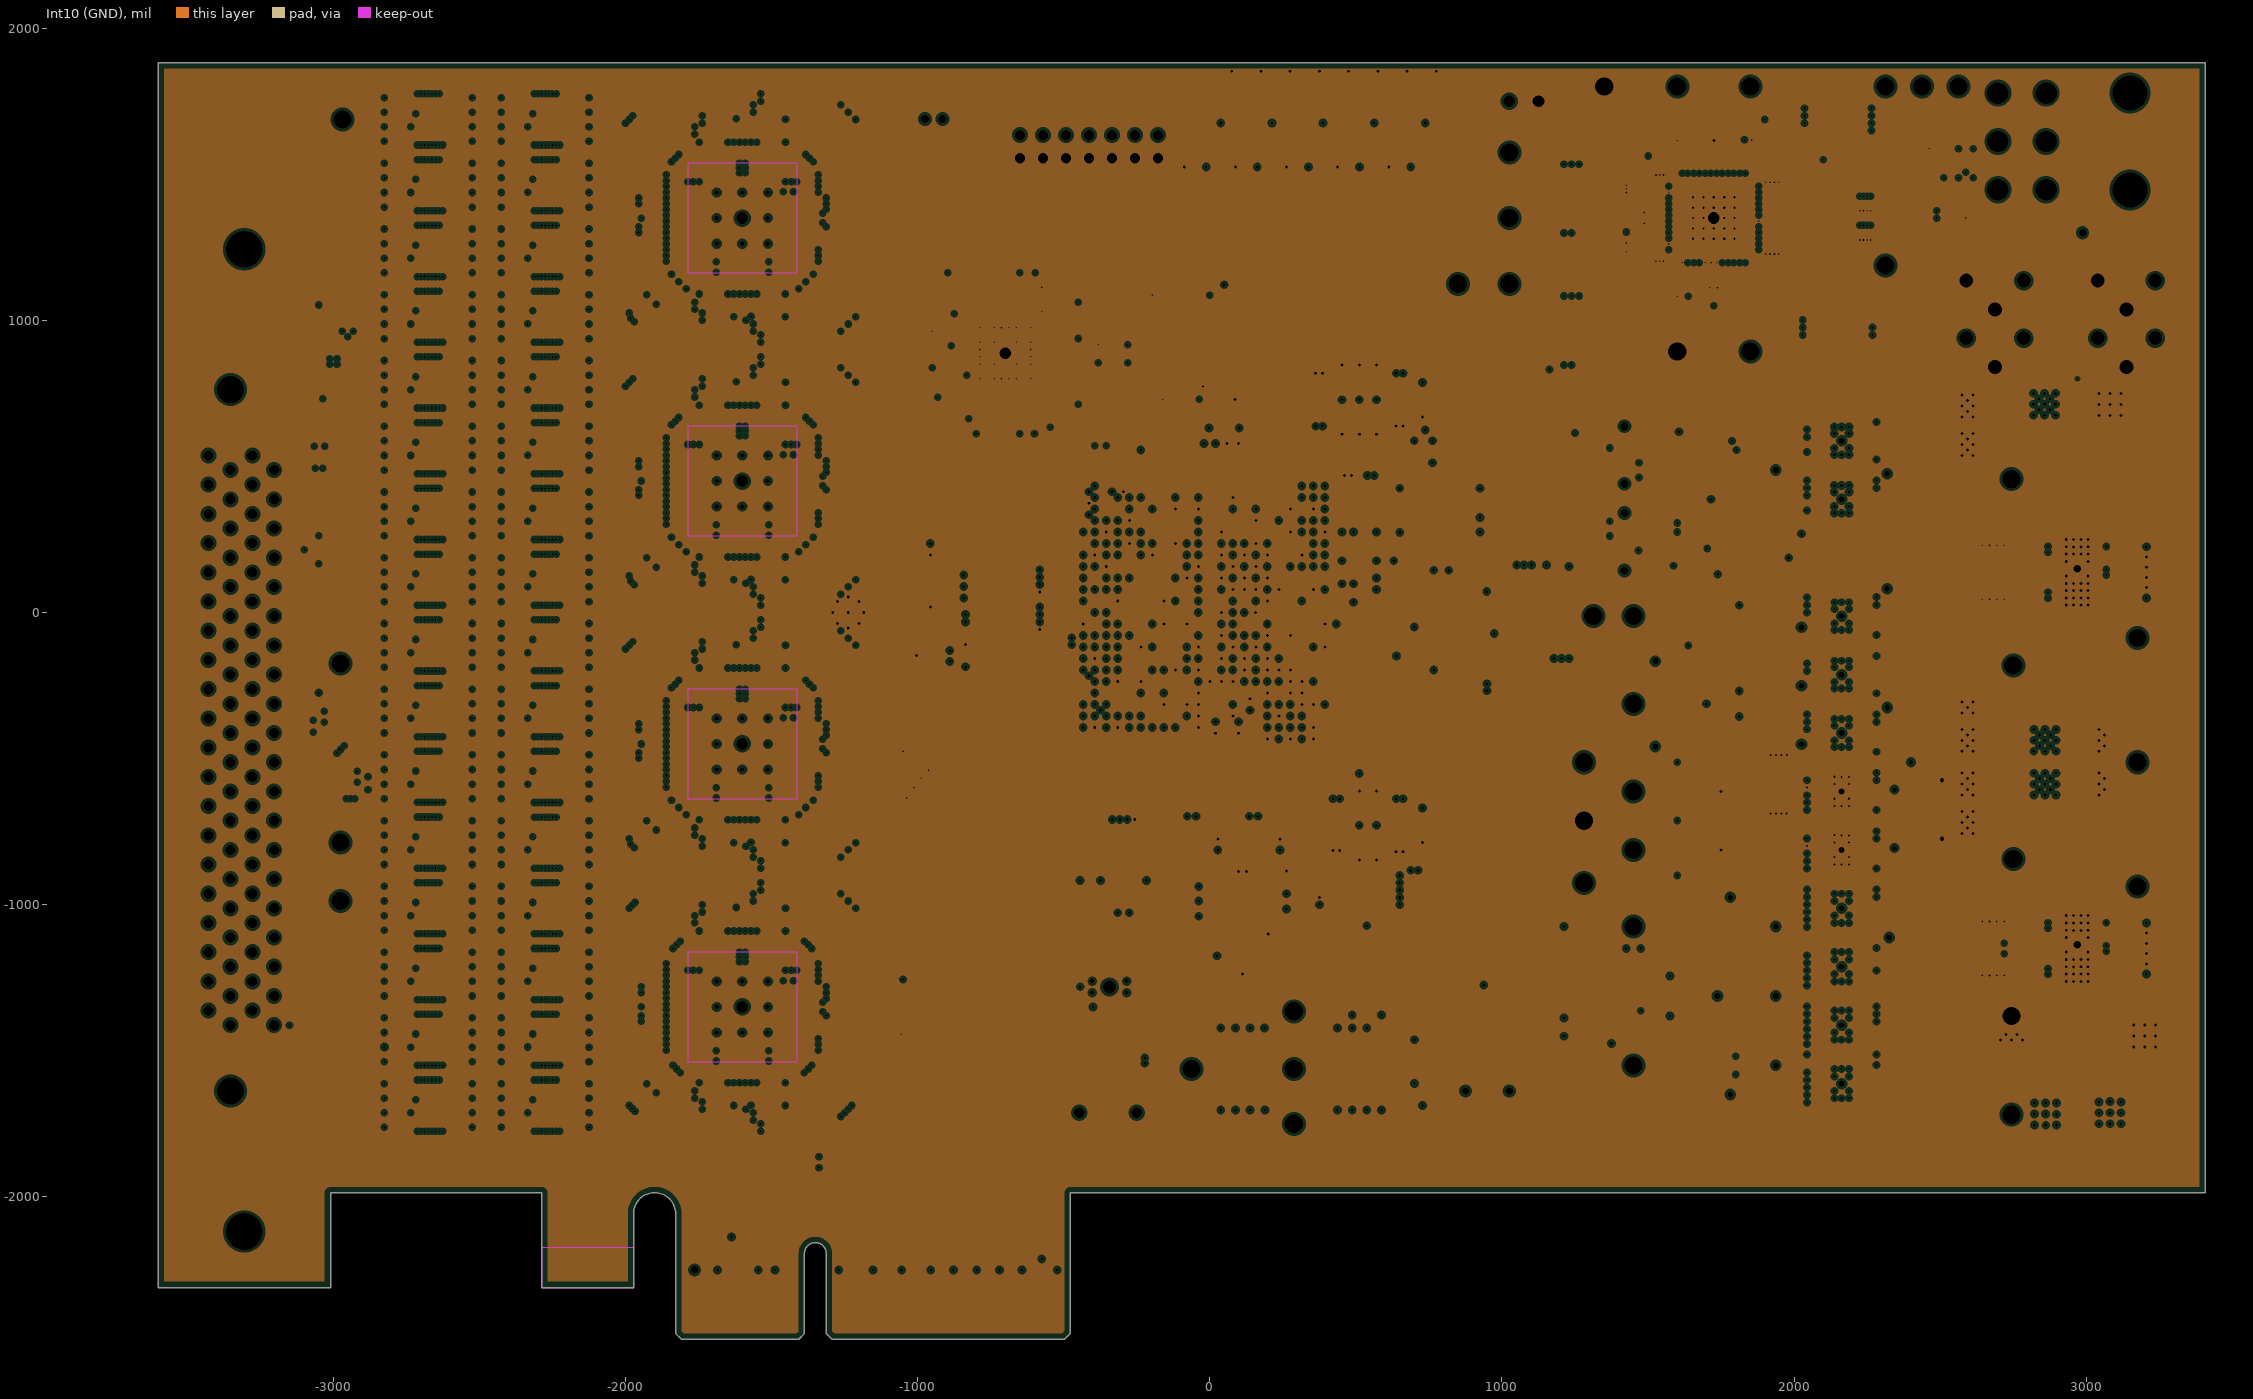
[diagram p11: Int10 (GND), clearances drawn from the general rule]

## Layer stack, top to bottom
Top Solder: solder mask 1, SM-001, Dk 4
Top Layer: signal copper 1.378
Dielectric 1: prepreg 3.8, PP-013, Dk 4.3
Int1 (GND): plane copper 1.378, net GND
Dielectric 2: core 4, Core-011, Dk 4.4
Int2 (AVDD): plane copper 1.378, net (Multiple Nets)
Dielectric 3: prepreg 3.8, PP-013, Dk 4.3
Int3 (DVDD): plane copper 1.378, net (Multiple Nets)
Dielectric 4: core 4, Core-011, Dk 4.4
Int4 (GND): plane copper 1.378, net (Multiple Nets)
Dielectric 5: prepreg 4.2, PP-014, Dk 4.2
Int5 (ST): signal copper 1.378
Dielectric 6: core 4, Core-011, Dk 4.4
Int6 (SB): signal copper 1.378
Dielectric 7: prepreg 4.2, PP-014, Dk 4.2
Int8 (AGND): plane copper 1.378, net (Multiple Nets)
Dielectric 8: core 4, Core-011, Dk 4.4
Int7 (AVCC): plane copper 1.378, net (Multiple Nets)
Dielectric 9: prepreg 3.8, PP-013, Dk 4.3
Int9 (VCCA): plane copper 1.378, net (Multiple Nets)
Dielectric 10: core 4, Core-011, Dk 4.4
Int10 (GND): plane copper 1.378, net GND
Dielectric 11: prepreg 3.8, PP-013, Dk 4.3
Bottom Layer: signal copper 1.378
Bottom Solder: solder mask 1, SM-001, Dk 4

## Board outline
-3600,-2310.33 -3009.45,-2310.33 -3009.45,-1985.53 -2287.01,-1985.53 -2287.01,-2310.33 -1972.05,-2310.33 -1972.05,-2057.38 cw(c-1900.2,-2057.38) -1828.35,-2057.38 -1828.35,-2467.81 -1808.66,-2487.5 -1407.09,-2487.5 -1387.4,-2467.81 -1387.4,-2194.19 cw(c-1350,-2194.19) -1312.6,-2194.19 -1312.6,-2467.81 -1292.91,-2487.5 -497.5,-2487.5 -477.5,-2467.5 -477.5,-1985.53 3407.87,-1985.53 3407.87,1881.35 -3600,1881.35

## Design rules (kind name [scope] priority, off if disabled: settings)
Clearance [All] p1: gap=6 ignorepadtopadclearanceinfootprint=TRUE except(0: Arc-Text Track-Text SMDPad-Text THPad-Text Via-Text Fill-Text Poly-Text Region-Text Text-Text Text-Hole; 2.99: Arc-Arc Arc-Track Arc-SMDPad Arc-THPad Arc-Via Arc-Hole Track-Track Track-SMDPad Track-THPad Track-Via Track-Hole SMDPad-SMDPad SMDPad-THPad SMDPad-Via SMDPad-Hole THPad-THPad THPad-Via THPad-Hole Via-Via Via-Hole)
ComponentClearance ComponentClearance_1 [InComponent('PCI-E Bracket') vs InComponent('Designator26')] p1: gap=10 collisioncheckmode=3 verticalgap=10 showdistances=FALSE
ComponentClearance [All] p2: gap=10 collisioncheckmode=3 verticalgap=10 showdistances=FALSE
DiffPairsRouting DiffPairsRouting_REFCLK [InDifferentialPairClass('PCIE Clocks')] p1: maxlimit=5 minlimit=4.4 mostfreqgap=5 toplayer_maxgap=4.4 toplayer_prefgap=4.4 toplayer_minwidth=4.2 toplayer_maxwidth=4.2 toplayer_prefwidth=4.2 midlayer1_mingap=5 midlayer1_minwidth=6 midlayer1_maxwidth=6 midlayer1_prefwidth=6 midlayer2_mingap=5 midlayer2_minwidth=6 midlayer2_maxwidth=6 midlayer2_prefwidth=6 bottomlayer_maxgap=4.4 bottomlayer_prefgap=4.4 bottomlayer_minwidth=4.2 bottomlayer_maxwidth=4.2 bottomlayer_prefwidth=4.2 maxuncoupledlength=19.68
DiffPairsRouting [All] p2: maxlimit=5 minlimit=2.99 mostfreqgap=5 toplayer_mingap=3 toplayer_maxgap=3 toplayer_prefgap=3 toplayer_minwidth=5 toplayer_maxwidth=5 toplayer_prefwidth=5 midlayer1_minwidth=5 midlayer1_maxwidth=6 midlayer1_prefwidth=6 midlayer2_minwidth=5 midlayer2_maxwidth=6 midlayer2_prefwidth=6 bottomlayer_mingap=3 bottomlayer_maxgap=3 bottomlayer_prefgap=3 bottomlayer_minwidth=5 bottomlayer_maxwidth=5 bottomlayer_prefwidth=5 maxuncoupledlength=19.68
FabricationTestPointUsage TestPointUsage [All] p1: valid=0 allowmultiple=FALSE
FabricationTestpoint Testpoint [All] p1: side=3 testpointundercomponent=TRUE minsize=40 maxsize=100 preferedsize=60 minholesize=20 maxholesize=40 preferedholesize=32 testpointgrid=1 allowsidetop=TRUE allowsidebottom=TRUE usegrid=TRUE gridtolerance=0.01
Height "PCI Express, Page 84, \"Component Height Constraints\" for solder side" [OnBottomLayer] p1: minheight=0 maxheight=105.12 prefheight=105.12
Height "PCI Express, Page 84, \"Component Height Constraints\" for component side" [OnTopLayer] p2: minheight=0 maxheight=569.68 prefheight=569.68
PlaneClearance [All] p1: clearance=10
PlaneConnect [All] p1: pad.planeconnectstyle=Relief pad.reliefexpansion=20 pad.reliefentries=4 pad.reliefconductorwidth=10 pad.reliefairgap=10 via.planeconnectstyle=Direct via.reliefexpansion=20 via.reliefentries=4 via.reliefconductorwidth=10 via.reliefairgap=10
PolygonConnect [All] p1: connectstyle=Direct reliefconductorwidth=10 reliefentries=4 polygonreliefangle="90 Angle" airgapwidth=10
RoomDefinition 4 [InComponentClass('4')] p1: confinementstyle=ConfineIn formatcopy=TRUE lockcomponents=FALSE outline -7537.01,-6424.51 -5537.01,-6424.51 -5537.01,-5424.51 -7537.01,-5424.51
RoomDefinition 1 [InComponentClass('1')] p2: confinementstyle=ConfineIn formatcopy=TRUE lockcomponents=FALSE outline -7537.01,-6424.51 -5537.01,-6424.51 -5537.01,-5424.51 -7537.01,-5424.51
RoomDefinition 4_1 [InComponentClass('4')] p3: confinementstyle=ConfineIn formatcopy=TRUE lockcomponents=FALSE outline -7537.01,-6424.51 -5537.01,-6424.51 -5537.01,-5424.51 -7537.01,-5424.51
RoomDefinition 1_1 [InComponentClass('1')] p4: confinementstyle=ConfineIn formatcopy=TRUE lockcomponents=FALSE outline -7537.01,-6424.51 -5537.01,-6424.51 -5537.01,-5424.51 -7537.01,-5424.51
RoomDefinition 2 [InComponentClass('2')] p5: confinementstyle=ConfineIn formatcopy=TRUE lockcomponents=FALSE outline -7537.01,-6424.51 -5537.01,-6424.51 -5537.01,-5424.51 -7537.01,-5424.51
RoomDefinition 3 [InComponentClass('3')] p6: confinementstyle=ConfineIn formatcopy=TRUE lockcomponents=FALSE outline -1162.5,-912.5 -2097.5,-912.5 -2097.5,-1787.5 -1162.5,-1787.5
RoomDefinition 2_1 [InComponentClass('2')] p7: confinementstyle=ConfineIn formatcopy=TRUE lockcomponents=FALSE outline -2100,1562.5 -2850,1562.5 -2850,1362.5 -2100,1362.5
RoomDefinition 3_1 [InComponentClass('3')] p8: confinementstyle=ConfineIn formatcopy=TRUE lockcomponents=FALSE outline -2100,1787.5 -2850,1787.5 -2850,1587.5 -2100,1587.5
RoomDefinition "Power Supplies" [InComponentClass('Power Supplies')] p9: confinementstyle=ConfineIn formatcopy=TRUE lockcomponents=FALSE outline 3452.99,-2529.51 4022.99,-2529.51 4022.99,-1369.51 3452.99,-1369.51
RoomDefinition ADC [InComponentClass('ADC')] p10: confinementstyle=ConfineIn formatcopy=TRUE lockcomponents=FALSE outline -7537.01,-6424.51 -5537.01,-6424.51 -5537.01,-5424.51 -7537.01,-5424.51
RoomDefinition LD32_TOP [InComponentClass('LD32_TOP')] p11: confinementstyle=ConfineIn formatcopy=TRUE lockcomponents=FALSE outline -7537.01,-6424.51 -5537.01,-6424.51 -5537.01,-5424.51 -7537.01,-5424.51
RoomDefinition "FPGA INTERFACE" [InComponentClass('FPGA INTERFACE')] p12: confinementstyle=ConfineIn formatcopy=TRUE lockcomponents=FALSE outline -7537.01,-6424.51 -5537.01,-6424.51 -5537.01,-5424.51 -7537.01,-5424.51
RoomDefinition FPGA [InComponentClass('FPGA')] p13: confinementstyle=ConfineIn formatcopy=TRUE lockcomponents=FALSE outline -7537.01,-6424.51 -5537.01,-6424.51 -5537.01,-5424.51 -7537.01,-5424.51
RoomDefinition "Diff Power" [InComponentClass('Diff Power')] p14: confinementstyle=ConfineIn formatcopy=TRUE lockcomponents=FALSE outline -2525,-4482.5 -5537.01,-4482.5 -5537.01,-5424.51 -2525,-5424.51
RoomDefinition "Pos Power" [InComponentClass('Pos Power')] p15: confinementstyle=ConfineIn formatcopy=TRUE lockcomponents=FALSE outline -2750,-4120 -5537.01,-4120 -5537.01,-5424.51 -2750,-5424.51
RoomDefinition "Linear Supplies" [InComponentClass('Linear Supplies')] p16: confinementstyle=ConfineIn formatcopy=TRUE lockcomponents=FALSE outline -2307.5,-4662.5 -5537.01,-4662.5 -5537.01,-5424.51 -2307.5,-5424.51
RoomDefinition Designator [InComponentClass('Designator')] p17: confinementstyle=ConfineIn formatcopy=TRUE lockcomponents=FALSE outline 3452.99,-2429.51 16827.99,-2429.51 16827.99,-1834.51 3452.99,-1834.51
RoomDefinition ChassisTimingInterfacePCIE [InComponentClass('ChassisTimingInterfacePCIE')] p18: confinementstyle=ConfineIn formatcopy=TRUE lockcomponents=FALSE outline -2820,-4050 -5537.01,-4050 -5537.01,-5424.51 -2820,-5424.51
RoomDefinition "VCO Phase" [InComponentClass('VCO Phase')] p19: confinementstyle=ConfineIn formatcopy=TRUE lockcomponents=FALSE outline 3452.99,-1337.01 14012.99,-1337.01 14012.99,-429.51 3452.99,-429.51
RoomDefinition PRG [InComponentClass('PRG')] p20: confinementstyle=ConfineIn formatcopy=TRUE lockcomponents=FALSE outline 3452.99,-1842.01 12747.99,-1842.01 12747.99,-1287.01 3452.99,-1287.01
RoomDefinition Analog [InComponentClass('Analog')] p21: confinementstyle=ConfineIn formatcopy=TRUE lockcomponents=FALSE outline -2935,-3980 -5537.01,-3980 -5537.01,-5424.51 -2935,-5424.51
RoomDefinition 16 [InComponentClass('16')] p22: confinementstyle=ConfineIn formatcopy=TRUE lockcomponents=FALSE outline -2100,-1587.5 -2850,-1587.5 -2850,-1787.5 -2100,-1787.5
RoomDefinition 15 [InComponentClass('15')] p23: confinementstyle=ConfineIn formatcopy=TRUE lockcomponents=FALSE outline -2100,-912.5 -2850,-912.5 -2850,-1112.5 -2100,-1112.5
RoomDefinition 14 [InComponentClass('14')] p24: confinementstyle=ConfineIn formatcopy=TRUE lockcomponents=FALSE outline -2100,-1137.5 -2850,-1137.5 -2850,-1337.5 -2100,-1337.5
RoomDefinition 13 [InComponentClass('13')] p25: confinementstyle=ConfineIn formatcopy=TRUE lockcomponents=FALSE outline -2100,-1362.5 -2850,-1362.5 -2850,-1562.5 -2100,-1562.5
RoomDefinition 12 [InComponentClass('12')] p26: confinementstyle=ConfineIn formatcopy=TRUE lockcomponents=FALSE outline -2100,-687.5 -2850,-687.5 -2850,-887.5 -2100,-887.5
RoomDefinition 11 [InComponentClass('11')] p27: confinementstyle=ConfineIn formatcopy=TRUE lockcomponents=FALSE outline -2100,-12.5 -2850,-12.5 -2850,-212.5 -2100,-212.5
RoomDefinition 10 [InComponentClass('10')] p28: confinementstyle=ConfineIn formatcopy=TRUE lockcomponents=FALSE outline -2100,-237.5 -2850,-237.5 -2850,-437.5 -2100,-437.5
RoomDefinition 9 [InComponentClass('9')] p29: confinementstyle=ConfineIn formatcopy=TRUE lockcomponents=FALSE outline -2100,-462.5 -2850,-462.5 -2850,-662.5 -2100,-662.5
RoomDefinition 8 [InComponentClass('8')] p30: confinementstyle=ConfineIn formatcopy=TRUE lockcomponents=FALSE outline -2100,212.5 -2850,212.5 -2850,12.5 -2100,12.5
RoomDefinition 7 [InComponentClass('7')] p31: confinementstyle=ConfineIn formatcopy=TRUE lockcomponents=FALSE outline -2100,887.5 -2850,887.5 -2850,687.5 -2100,687.5
RoomDefinition 6 [InComponentClass('6')] p32: confinementstyle=ConfineIn formatcopy=TRUE lockcomponents=FALSE outline -2100,662.5 -2850,662.5 -2850,462.5 -2100,462.5
RoomDefinition 5 [InComponentClass('5')] p33: confinementstyle=ConfineIn formatcopy=TRUE lockcomponents=FALSE outline -2100,437.5 -2850,437.5 -2850,237.5 -2100,237.5
RoomDefinition PowerFPGA [InComponentClass('PowerFPGA')] p34: confinementstyle=ConfineIn formatcopy=TRUE lockcomponents=FALSE outline 3375,1850 1050,1850 1050,800 3375,800
RoutingCorners [All] p1: cornerstyle=Round minsetback=100 maxsetback=100
RoutingVias [All] p1: holewidth=10 width=20 viastyle="Through Hole" minholewidth=8 minwidth=16 maxholewidth=28 maxwidth=50
SilkToSolderMaskClearance SilkscreenOverComponentPads [IsPad] p1: minsilkscreentomaskgap=10 clearancetoexposedcopper=TRUE
SolderMaskExpansion [All] p1: expansion=0 istentingtop=FALSE
SupplyNets "Schematic Supply Nets_35" [InNet('AVCCL3.3V')] p1: voltage=0.000
SupplyNets "Schematic Supply Nets_34" [InNet('VCCA3.3V')] p2: voltage=0.000
SupplyNets "Schematic Supply Nets_33" [InNet('AGND')] p3: voltage=0.000
SupplyNets "Schematic Supply Nets_32" [InNet('GND')] p4: voltage=0.000
SupplyNets "Schematic Supply Nets_31" [InNet('+7V')] p5: voltage=0.000
SupplyNets "Schematic Supply Nets_30" [InNet('VREF-PH')] p6: voltage=0.000
SupplyNets "Schematic Supply Nets_29" [InNet('BUS12V')] p7: voltage=0.000
SupplyNets "Schematic Supply Nets_28" [InNet('EXTGND')] p8: voltage=0.000
SupplyNets "Schematic Supply Nets_27" [InNet('AVCC3.3V')] p9: voltage=0.000
SupplyNets "Schematic Supply Nets_26" [InNet('VCC')] p10: voltage=0.000
SupplyNets "Schematic Supply Nets_25" [InNet('XADCVCC')] p11: voltage=0.000
SupplyNets "Schematic Supply Nets_24" [InNet('AVCC')] p12: voltage=0.000
SupplyNets "Schematic Supply Nets_23" [InNet('VCC2')] p13: voltage=0.000
SupplyNets "Schematic Supply Nets_22" [InNet('VREG')] p14: voltage=0.000
SupplyNets "Schematic Supply Nets_21" [InNet('EXT12V')] p15: voltage=0.000
SupplyNets "Schematic Supply Nets_20" [InNet('VCC1V0')] p16: voltage=0.000
SupplyNets "Schematic Supply Nets_19" [InNet('-7V')] p17: voltage=0.000
SupplyNets "Schematic Supply Nets_18" [InNet('VREF1.28')] p18: voltage=0.000
SupplyNets "Schematic Supply Nets_17" [InNet('SW+4V')] p19: voltage=0.000
SupplyNets "Schematic Supply Nets_16" [InNet('VCC2V5')] p20: voltage=0.000
SupplyNets "Schematic Supply Nets_15" [InNet('SW+2V')] p21: voltage=0.000
SupplyNets "Schematic Supply Nets_14" [InNet('12VF')] p22: voltage=0.000
SupplyNets "Schematic Supply Nets_13" [InNet('AVTT')] p23: voltage=0.000
SupplyNets "Schematic Supply Nets_12" [InNet('AVCCR3.3V')] p24: voltage=0.000
SupplyNets "Schematic Supply Nets_11" [InNet('VCCAUX')] p25: voltage=0.000
SupplyNets "Schematic Supply Nets_10" [InNet('XADCGND')] p26: voltage=0.000
SupplyNets "Schematic Supply Nets_9" [InNet('VREF-COM')] p27: voltage=0.000
SupplyNets "Schematic Supply Nets_8" [InNet('BUS3.3V')] p28: voltage=0.000
SupplyNets "Schematic Supply Nets_7" [InNet('VREG2')] p29: voltage=0.000
SupplyNets "Schematic Supply Nets_6" [InNet('SENS_120f_N')] p30: voltage=0.000
SupplyNets "Schematic Supply Nets_5" [InNet('AVCC1V8')] p31: voltage=0.000
SupplyNets "Schematic Supply Nets_4" [InNet('DVDD1.2V')] p32: voltage=0.000
SupplyNets "Schematic Supply Nets_3" [InNet('DVDDR1.2V')] p33: voltage=0.000
SupplyNets "Schematic Supply Nets_2" [InNet('12VA')] p34: voltage=0.000
SupplyNets "Schematic Supply Nets_1" [InNet('12V')] p35: voltage=0.000
SupplyNets "Schematic Supply Nets" [InNet('DVDDL1.2V')] p36: voltage=0.000
Width [All] p1: maxlimit=196.85 minlimit=3 preferedwidth=10 checkconnectedcopper=TRUE
21 further rules are at their usual default settings.

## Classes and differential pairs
net class EXTCLK.XMUX[3..0]: EXTCLK.XMUX0 EXTCLK.XMUX1 EXTCLK.XMUX2 EXTCLK.XMUX3
component class "Power Supplies": MP5 MP6 MP7 MP8
net class PG[9..0]: PG0 PG1 PG2 PG3 PG4 PG5 PG6 PG7 PG8 PG9
channel class LD32_Outputs: I1 I2 I3 I4
channel class LD32_FrontEnd: 1 2 3 4 5 6 7 8 9 10 11 12 13 14 15 16
channel class LD32_DAC: 1 2 3 4
component class PRG: C65 C66 C68 C69 C212 C257 DS1 J1 P3 Q1 R67 R68 R69 R70 R71 R72 R73 R82 R83 R84 R85 R88 R89 R90 R96 R98 R99 R100 R101 R104 R105 R106 R107 R109 R293 R294 R297 R298 R299 R300 R301 R302 R304 U39 U40 U47 Y1
component class FPGA: C72 C73 C74 C75 C76 C77 C78 C79 C80 C81 C82 C83 C84 C85 C91 C92 C182 C183 C185 C186 C189 C190 C191 C192 C199 C200 C201 C202 C204 C205 C206 C207 C208 C209 C214 C218 C219 C221 C222 C223 C224 C225 C226 C227 C228 C234 C235 C236 C237 C241 C242 C243 C244 C246 C247 C250 C251 C252 C253 C254 C255 C256 C258 C259 C260 C261 C262 C263 C264 C265 C269 C270 C271 C273 DS2 DS3 DS4 DS5 DS6 Q6 Q7 Q8 Q9 Q10 R280 R281 R285 R286 R288 R289 R290 R291 R295 R296
component class "FPGA INTERFACE": R287 U45
net class JTAG[1..5]: JTAG1 JTAG2 JTAG3 JTAG4 JTAG5
component class Designator: C148 C149 C153 C154 C159 C160 C172 C173 C210 C211 C213 C216 C220 C229 C231 C238 C239 C240 C268 C274 C275 C276 C277 C278 C279 C280 C282 C284 C285 C286 D3 FL1 FL2 J2 L9 L10 R162 R163 R170 R171 R182 R183 R199 R222 R237 R238 R316 R317 R318 TP19 TP20 TP29 TP30 U70 U71 U88
component class ChassisTimingInterfacePCIE: P2
net class XMUX[3..0]: SQSPI.XMUX0 SQSPI.XMUX1 SQSPI.XMUX2 SQSPI.XMUX3
net class SW[8..1]: SW1 SW2 SW3 SW4 SW5 SW6 SW7 SW8
component class "VCO Phase": C61 C64 C67 C70 C71 C86 C87 C88 C89 C90 C188 C195 C196 C198 C215 C217 C230 C232 C245 C248 C249 C266 C267 C272 FR9 R87 R91 R92 R93 R94 R95 R97 R102 R103 R108 R110 R111 R112 R113 R115 R116 R117 R284 R292 R303 TP4 TP5 TP6 TP7 TP39 TP40 U44 U46 U48 U49 U50 U51 U52 U53 U54 U55
component class ADC: C93 C94 C95 C96 C97 C105 C146 C152 C155 C177 C178 C179 C180 C181 C184 C187 C193 C194 C197 C203 C233 FR1 FR2 FR3 FR6 FR7 FR8 Q3 Q4 Q5 R114 R118 R119 R120 R121 R122 R123 R124 R125 R126 R127 R130 R131 R132 R133 R134 R135 R136 R137 R138 R139 R140 R141 R142 R143 R161 R169 R175 R176 R184 R185 R195 R196 R197 R198 R200 R221 R223 R229 R230 R235 R247 R253 R254 R255 R257 R258 R259 R274 R275 R279 R282 R283 TP8 U56 U57 U58 U59 U60 U61 U62 U63 U65 U78 U79 U80 U81 U87 W3
component class LD32_TOP: C59 C60 C62 C63 C281 C283 LOGO1 P1 R74 R75 R76 R77 R78 R79 R80 R81 R86 R305 R306 R307 R308 R309 R310 R311 R312 R313 R314 R315 S1 U41 U42 U43
component class "Pos Power": C120 C121 C124 C125 C126 C127 C130 C132 C135 C136 C138 C140 C143 C144 C145 D5 D6 FR5 L6 L8 R203 R204 R206 R210 R212 R216 R217 R218 R219 R227 R228 TP33 TP35 TP38 U83 W2
component class "Linear Supplies": C9 C10 C11 C12 C13 C14 C98 C99 C116 C117 C156 C161 C162 C167 C168 C169 C170 C171 C500 R149 R150 R151 R152 R160 R164 R172 R177 R178 R179 R190 R191 R192 R193 R194 R231 R239 R240 R243 R244 R245 R262 R270 R272 R273 R276 R277 R500 TP12 TP14 TP15 TP21 TP22 U72 U73 U74 U75 U76 U77 U84 U85 U86
component class PowerFPGA: C100 C101 C102 C103 C104 C106 C107 C108 C109 C110 C111 C112 C113 C114 C115 C147 C163 C164 C174 C175 C176 L1 L2 L3 L4 P4 Q2 R128 R129 R144 R145 R146 R147 R148 R153 R154 R155 R156 R157 R158 R159 R173 R187 R188 R189 R224 R246 R250 R251 R252 R256 R260 R261 R263 R264 R265 R266 R267 R268 R269 R271 R278 TP9 TP10 TP11 TP13 TP16 TP23 TP24 TP25 TP26 TP27 TP28 U64
component class 16: C319P C335P C351P C367P C383P C399P C415P C431P C447P C463P R7P R8P R335P R351P R367P R383P R399P R415P R431P R447P U3P U19P
component class 15: C319O C335O C351O C367O C383O C399O C415O C431O C447O C463O R7O R8O R335O R351O R367O R383O R399O R415O R431O R447O U3O U19O
component class 14: C319N C335N C351N C367N C383N C399N C415N C431N C447N C463N R7N R8N R335N R351N R367N R383N R399N R415N R431N R447N U3N U19N
component class 13: C319M C335M C351M C367M C383M C399M C415M C431M C447M C463M R7M R8M R335M R351M R367M R383M R399M R415M R431M R447M U3M U19M
component class 12: C319L C335L C351L C367L C383L C399L C415L C431L C447L C463L R7L R8L R335L R351L R367L R383L R399L R415L R431L R447L U3L U19L
component class 11: C319K C335K C351K C367K C383K C399K C415K C431K C447K C463K R7K R8K R335K R351K R367K R383K R399K R415K R431K R447K U3K U19K
component class 10: C319J C335J C351J C367J C383J C399J C415J C431J C447J C463J R7J R8J R335J R351J R367J R383J R399J R415J R431J R447J U3J U19J
component class 9: C319I C335I C351I C367I C383I C399I C415I C431I C447I C463I R7I R8I R335I R351I R367I R383I R399I R415I R431I R447I U3I U19I
component class 8: C319H C335H C351H C367H C383H C399H C415H C431H C447H C463H R7H R8H R335H R351H R367H R383H R399H R415H R431H R447H U3H U19H
component class 7: C319G C335G C351G C367G C383G C399G C415G C431G C447G C463G R7G R8G R335G R351G R367G R383G R399G R415G R431G R447G U3G U19G
component class 6: C319F C335F C351F C367F C383F C399F C415F C431F C447F C463F R7F R8F R335F R351F R367F R383F R399F R415F R431F R447F U3F U19F
component class 5: C319E C335E C351E C367E C383E C399E C415E C431E C447E C463E R7E R8E R335E R351E R367E R383E R399E R415E R431E R447E U3E U19E
component class 4: C319D C335D C351D C367D C383D C399D C415D C431D C447D C463D R7D R8D R335D R351D R367D R383D R399D R415D R431D R447D U3D U19D
component class 3: C319C C335C C351C C367C C383C C399C C415C C431C C447C C463C R7C R8C R335C R351C R367C R383C R399C R415C R431C R447C U3C U19C
component class 2: C319B C335B C351B C367B C383B C399B C415B C431B C447B C463B R7B R8B R335B R351B R367B R383B R399B R415B R431B R447B U3B U19B
component class 1: C319A C335A C351A C367A C383A C399A C415A C431A C447A C463A R7A R8A R335A R351A R367A R383A R399A R415A R431A R447A U3A U19A
component class 4: C7D C8D C15D C19D C20D C27D C31D C35D C36D C43D C44D C51D C52D C287D C291D C295D C299D C303D C307D C311D C315D MP4D R39D R40D R41D R42D R55D R56D R63D R319D R323D R327D R331D TP41D TP45D U35D U89D U93D
component class 3: C7C C8C C15C C19C C20C C27C C31C C35C C36C C43C C44C C51C C52C C287C C291C C295C C299C C303C C307C C311C C315C MP4C R39C R40C R41C R42C R55C R56C R63C R319C R323C R327C R331C TP41C TP45C U35C U89C U93C
component class 2: C7B C8B C15B C19B C20B C27B C31B C35B C36B C43B C44B C51B C52B C287B C291B C295B C299B C303B C307B C311B C315B MP4B R39B R40B R41B R42B R55B R56B R63B R319B R323B R327B R331B TP41B TP45B U35B U89B U93B
component class "Diff Power": C118 C119 C122 C123 C128 C129 C131 C133 C134 C137 C139 C141 C142 C150 C151 C157 C158 C165 C166 C481 C482 C483 C484 D4 D7 D8 D9 FR4 L5 L7 R165 R166 R167 R168 R174 R180 R181 R186 R201 R202 R205 R207 R208 R209 R211 R213 R214 R215 R220 R225 R226 R232 R233 R234 R236 R241 R242 R248 R249 TP17 TP18 TP31 TP32 TP34 TP36 TP37 U66 U67 U68 U69 U82 W1
component class 1: C7A C8A C15A C19A C20A C27A C31A C35A C36A C43A C44A C51A C52A C287A C291A C295A C299A C303A C307A C311A C315A MP4A R39A R40A R41A R42A R55A R56A R63A R319A R323A R327A R331A TP41A TP45A U35A U89A U93A
component class Analog: C1 C2 C3 C4 C5 C6 C479 C480 D1 D2 R1 R2 R3 R4 R5 R6 TP1 TP2 TP3 TP42 U1 U2
differential pair EXTCLK.CAUX: +EXTCLK.CAUX_P -EXTCLK.CAUX_N
differential pair CAUX: +CAUX_P -CAUX_N
differential pair CLK_AUX: +CLK_AUX_P -CLK_AUX_N
differential pair D8D: +D8D_P -D8D_N
differential pair D8C: +D8C_P -D8C_N
differential pair D8B: +D8B_P -D8B_N
differential pair D8A: +D8A_P -D8A_N
differential pair D7D: +D7D_P -D7D_N
differential pair D7C: +D7C_P -D7C_N
differential pair D7B: +D7B_P -D7B_N
differential pair D7A: +D7A_P -D7A_N
differential pair D6D: +D6D_P -D6D_N
differential pair D6C: +D6C_P -D6C_N
differential pair D6B: +D6B_P -D6B_N
differential pair D6A: +D6A_P -D6A_N
differential pair D5D: +D5D_P -D5D_N
differential pair D5C: +D5C_P -D5C_N
differential pair D5B: +D5B_P -D5B_N
differential pair D5A: +D5A_P -D5A_N
differential pair D4D: +D4D_P -D4D_N
differential pair D4C: +D4C_P -D4C_N
differential pair D4B: +D4B_P -D4B_N
differential pair D4A: +D4A_P -D4A_N
differential pair D3D: +D3D_P -D3D_N
differential pair D3C: +D3C_P -D3C_N
differential pair D3B: +D3B_P -D3B_N
differential pair D3A: +D3A_P -D3A_N
differential pair D2D: +D2D_P -D2D_N
differential pair D2C: +D2C_P -D2C_N
differential pair D2B: +D2B_P -D2B_N
differential pair D2A: +D2A_P -D2A_N
differential pair D1D: +D1D_P -D1D_N
differential pair D1C: +D1C_P -D1C_N
differential pair D1B: +D1B_P -D1B_N
differential pair D1A: +D1A_P -D1A_N
differential pair EXT.TRIGout: +EXT.TRIGout_P -EXT.TRIGout_N
differential pair TRG: +TRG_P -TRG_N
differential pair CLKO: +CLKO_P -CLKO_N
differential pair CLKE: +CLKE_P -CLKE_N
differential pair CLK_O: +CLK_O_P -CLK_O_N
differential pair CLK_E: +CLK_E_P -CLK_E_N
differential pair DAC3.DCLK: +DAC3.DCLK_P -DAC3.DCLK_N
differential pair DAC2.DCLK: +DAC2.DCLK_P -DAC2.DCLK_N
differential pair DAC1.DCLK: +DAC1.DCLK_P -DAC1.DCLK_N
differential pair XADC: +XADC_P -XADC_N
differential pair XADC_REF: +XADC_REF_P -XADC_REF_N
differential pair PCIE.PCIE_TX3: +PCIE.PCIE_TX3_P -PCIE.PCIE_TX3_N
differential pair PCIE.PCIE_TX2: +PCIE.PCIE_TX2_P -PCIE.PCIE_TX2_N
differential pair PCIE.PCIE_TX1: +PCIE.PCIE_TX1_P -PCIE.PCIE_TX1_N
differential pair PCIE.PCIE_RX3: +PCIE.PCIE_RX3_P -PCIE.PCIE_RX3_N
differential pair PCIE.PCIE_RX2: +PCIE.PCIE_RX2_P -PCIE.PCIE_RX2_N
differential pair PCIE.PCIE_RX1: +PCIE.PCIE_RX1_P -PCIE.PCIE_RX1_N
differential pair PCIE.PCIE_TX0: +PCIE.PCIE_TX0_P -PCIE.PCIE_TX0_N
differential pair PCIE.PCIE_CLK: +PCIE.PCIE_CLK_P -PCIE.PCIE_CLK_N
differential pair PER3: +PER3_P -PER3_N
differential pair PER2: +PER2_P -PER2_N
differential pair PER1: +PER1_P -PER1_N
differential pair CLOCK.SYNC: +CLOCK.SYNC_P -CLOCK.SYNC_N
differential pair CLOCK.OSCCLK: +CLOCK.OSCCLK_P -CLOCK.OSCCLK_N
differential pair CLOCK.CNTROUT: +CLOCK.CNTROUT_P -CLOCK.CNTROUT_N
differential pair ANALOG4.A8: +ANALOG4.A8_P -ANALOG4.A8_N
differential pair ANALOG4.A7: +ANALOG4.A7_P -ANALOG4.A7_N
differential pair ANALOG4.A6: +ANALOG4.A6_P -ANALOG4.A6_N
differential pair ANALOG4.A5: +ANALOG4.A5_P -ANALOG4.A5_N
differential pair ANALOG4.A4: +ANALOG4.A4_P -ANALOG4.A4_N
differential pair ANALOG4.A3: +ANALOG4.A3_P -ANALOG4.A3_N
differential pair ANALOG4.A2: +ANALOG4.A2_P -ANALOG4.A2_N
differential pair ANALOG4.A1: +ANALOG4.A1_P -ANALOG4.A1_N
differential pair ANALOG3.A8: +ANALOG3.A8_P -ANALOG3.A8_N
differential pair ANALOG3.A7: +ANALOG3.A7_P -ANALOG3.A7_N
differential pair ANALOG3.A6: +ANALOG3.A6_P -ANALOG3.A6_N
differential pair ANALOG3.A5: +ANALOG3.A5_P -ANALOG3.A5_N
differential pair ANALOG3.A4: +ANALOG3.A4_P -ANALOG3.A4_N
differential pair ANALOG3.A3: +ANALOG3.A3_P -ANALOG3.A3_N
differential pair ANALOG3.A2: +ANALOG3.A2_P -ANALOG3.A2_N
differential pair ANALOG3.A1: +ANALOG3.A1_P -ANALOG3.A1_N
differential pair ANALOG2.A8: +ANALOG2.A8_P -ANALOG2.A8_N
differential pair ANALOG2.A7: +ANALOG2.A7_P -ANALOG2.A7_N
differential pair ANALOG2.A6: +ANALOG2.A6_P -ANALOG2.A6_N
differential pair ANALOG2.A5: +ANALOG2.A5_P -ANALOG2.A5_N
differential pair ANALOG2.A4: +ANALOG2.A4_P -ANALOG2.A4_N
differential pair ANALOG2.A3: +ANALOG2.A3_P -ANALOG2.A3_N
differential pair ANALOG2.A2: +ANALOG2.A2_P -ANALOG2.A2_N
differential pair ANALOG2.A1: +ANALOG2.A1_P -ANALOG2.A1_N
differential pair ANALOG1.A8: +ANALOG1.A8_P -ANALOG1.A8_N
differential pair ANALOG1.A7: +ANALOG1.A7_P -ANALOG1.A7_N
differential pair ANALOG1.A6: +ANALOG1.A6_P -ANALOG1.A6_N
differential pair ANALOG1.A5: +ANALOG1.A5_P -ANALOG1.A5_N
differential pair ANALOG1.A4: +ANALOG1.A4_P -ANALOG1.A4_N
differential pair ANALOG1.A3: +ANALOG1.A3_P -ANALOG1.A3_N
differential pair ANALOG1.A2: +ANALOG1.A2_P -ANALOG1.A2_N
differential pair ANALOG1.A1: +ANALOG1.A1_P -ANALOG1.A1_N
differential pair REFCLK: +REFCLK_P -REFCLK_N
differential pair DAC4.DCLK: +DAC4.DCLK_P -DAC4.DCLK_N
differential pair PER0: +PER0_P -PER0_N
differential pair VCOCLK: +VCOCLK_P -VCOCLK_N
differential pair PCIE.PCIE_RX0: +PCIE.PCIE_RX0_P -PCIE.PCIE_RX0_N

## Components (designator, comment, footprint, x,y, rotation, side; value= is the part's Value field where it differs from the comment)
C1 "22uF" CC5650-2220 -2975,112.5 r270 top value="22uF Film"
C2 "NL" CC1005-0402 -3037.5,350 r0 top
C3 "10uF" CC3225-1210 -2975,1150 r180 top value=10uf
C4 "NL" CC1608-0603 -2975,-662.5 r0 top
C5 "10uF" CC3225-1210 -2975,650 r0 top value=10uf
C6 "NL" CC1608-0603 -2975,-275 r180 top
C7A "10uf" CC3225-1210 -1887.5,1062.5 r45 top locked (schematic designator C7)
C7B "10uf" CC3225-1210 -1887.5,162.5 r45 top locked (schematic designator C7)
C7C "10uf" CC3225-1210 -1887.5,-737.5 r45 top locked (schematic designator C7)
C7D "10uf" CC3225-1210 -1887.5,-1637.5 r45 top locked (schematic designator C7)
C8A "10uf" CC3225-1210 -1887.5,1637.5 r135 top locked (schematic designator C8)
C8B "10uf" CC3225-1210 -1887.5,737.5 r135 top locked (schematic designator C8)
C8C "10uf" CC3225-1210 -1887.5,-162.5 r135 top locked (schematic designator C8)
C8D "10uf" CC3225-1210 -1887.5,-1062.5 r135 top locked (schematic designator C8)
C9 "100nF" CC0603-0201 1587.5,187.5 r270 bottom
C10 "100nF" CC0603-0201 1775,556.25 r0 bottom
C11 "100nF" CC0603-0201 1250,587.5 r90 bottom
C12 "100nF" CC0603-0201 1675,218.75 r0 bottom
C13 "100nF" CC0603-0201 1587.5,487.5 r90 bottom
C14 "100nF" CC0603-0201 1250,287.5 r270 bottom
C15A "100nF" CC0603-0201 -1912.5,1350 r0 top (schematic designator C15)
C15B "100nF" CC0603-0201 -1912.5,450 r0 top locked (schematic designator C15)
C15C "100nF" CC0603-0201 -1912.5,-450 r0 top locked (schematic designator C15)
C15D "100nF" CC0603-0201 -1912.5,-1350 r0 top locked (schematic designator C15)
C19A "100nF" CC0603-0201 -1887.5,1212.5 r270 top locked (schematic designator C19)
C19B "100nF" CC0603-0201 -1887.5,312.5 r270 top locked (schematic designator C19)
C19C "100nF" CC0603-0201 -1887.5,-587.5 r270 top locked (schematic designator C19)
C19D "100nF" CC0603-0201 -1887.5,-1487.5 r270 top locked (schematic designator C19)
C20A "100nF" CC0603-0201 -1887.5,1487.5 r90 top locked (schematic designator C20)
C20B "100nF" CC0603-0201 -1887.5,587.5 r90 top locked (schematic designator C20)
C20C "100nF" CC0603-0201 -1887.5,-312.5 r90 top locked (schematic designator C20)
C20D "100nF" CC0603-0201 -1887.5,-1212.5 r90 top locked (schematic designator C20)
C27A "100nF" CC0603-0201 -1629.53,1050 r90 top locked (schematic designator C27)
C27B "100nF" CC0603-0201 -1629.53,150 r90 top locked (schematic designator C27)
C27C "100nF" CC0603-0201 -1629.53,-750 r90 top locked (schematic designator C27)
C27D "100nF" CC0603-0201 -1629.53,-1650 r90 top locked (schematic designator C27)
C31A "100nF" CC0603-0201 -1570.47,1050 r90 top locked (schematic designator C31)
C31B "100nF" CC0603-0201 -1570.47,150 r90 top locked (schematic designator C31)
C31C "100nF" CC0603-0201 -1570.47,-750 r90 top locked (schematic designator C31)
C31D "100nF" CC0603-0201 -1570.47,-1650 r90 top locked (schematic designator C31)
C35A "100nF" CC0603-0201 -1452.21,1050 r270 top locked (schematic designator C35)
C35B "100nF" CC0603-0201 -1452.21,150 r270 top locked (schematic designator C35)
C35C "100nF" CC0603-0201 -1452.21,-750 r270 top locked (schematic designator C35)
C35D "100nF" CC0603-0201 -1452.21,-1650 r270 top locked (schematic designator C35)
C36A "100nF" CC0603-0201 -1452.21,1650 r90 top locked (schematic designator C36)
C36B "100nF" CC0603-0201 -1452.21,750 r90 top locked (schematic designator C36)
C36C "100nF" CC0603-0201 -1452.21,-150 r90 top locked (schematic designator C36)
C36D "100nF" CC0603-0201 -1452.21,-1050 r90 top locked (schematic designator C36)
C43A "10uf" CC3225-1210 -1312.5,1062.5 r315 top locked (schematic designator C43)
C43B "10uf" CC3225-1210 -1312.5,162.5 r315 top locked (schematic designator C43)
C43C "10uf" CC3225-1210 -1312.5,-737.5 r315 top locked (schematic designator C43)
C43D "10uf" CC3225-1210 -1312.5,-1637.5 r315 top (schematic designator C43)
C44A "10uf" CC3225-1210 -1312.5,1637.5 r225 top locked (schematic designator C44)
C44B "10uf" CC3225-1210 -1312.5,737.5 r225 top locked (schematic designator C44)
C44C "10uf" CC3225-1210 -1312.5,-162.5 r225 top locked (schematic designator C44)
C44D "10uf" CC3225-1210 -1312.5,-1062.5 r225 top locked (schematic designator C44)
C51A "100nF" CC0603-0201 -1312.5,1212.5 r270 top locked (schematic designator C51)
C51B "100nF" CC0603-0201 -1312.5,312.5 r270 top locked (schematic designator C51)
C51C "100nF" CC0603-0201 -1312.5,-587.5 r270 top locked (schematic designator C51)
C51D "100nF" CC0603-0201 -1312.5,-1487.5 r270 top locked (schematic designator C51)
C52A "100nF" CC0603-0201 -1312.5,1487.5 r90 top locked (schematic designator C52)
C52B "100nF" CC0603-0201 -1312.5,587.5 r90 top locked (schematic designator C52)
C52C "100nF" CC0603-0201 -1312.5,-312.5 r90 top locked (schematic designator C52)
C52D "100nF" CC0603-0201 -1312.5,-1212.5 r90 top locked (schematic designator C52)
C59 "100nF" CC1005-0402 -905.51,88.58 r0 top
C60 "100nF" CC1005-0402 -905.51,127.95 r0 top
C61 "470nF poly" ECQPZ120060-5.0 -250,-1712.5 r180 top
C62 "100nF" CC1005-0402 -551.18,108.27 r90 top
C63 "100nF" CC1005-0402 -551.18,-19.68 r90 top
C64 "100nF" CC1005-0402 -444.88,-964.57 r270 top
C65 "100nF" CC1608-0603 -98.43,729.58 r0 top
C66 "100nF" CC1005-0402 -123.43,1060.83 r270 top
C67 "1.0nF COG" CC1005-0402 -62.5,-1712.5 r180 top
C68 "100nF" CC1005-0402 -73.43,1060.83 r270 top
C69 "10nF" CC1005-0402 -23.43,823.33 r90 top
C70 "1.0nF COG" CC1005-0402 87.5,-1262.5 r270 top
C71 "1.0nF COG" CC1005-0402 137.5,-1262.5 r90 top
C72 "47uF" CC3216-1206 374.02,728.35 r270 top
C73 "47uF" CC3216-1206 433.07,-728.35 r90 top
C74 "4.7uF" CC1608-0603 452.76,669.29 r90 top
C75 "4.7uF" CC1608-0603 452.76,787.4 r270 top
C76 "4.7uF" CC1608-0603 511.81,-669.29 r270 top
C77 "4.7uF" CC1608-0603 511.81,-787.4 r90 top
C78 "4.7uF" CC1608-0603 511.81,669.29 r90 top
C79 "4.7uF" CC1608-0603 511.81,787.4 r270 top
C80 "4.7uF" CC1608-0603 570.87,-787.4 r90 top
C81 "4.7uF" CC1608-0603 570.87,-669.29 r270 top
C82 "4.7uF" CC1608-0603 570.87,669.29 r90 top
C83 "4.7uF" CC1608-0603 570.87,787.4 r270 top
C84 "47uF" CC3216-1206 649.61,-728.35 r90 top
C85 "47uF" CC3216-1206 649.61,728.35 r90 top
C86 "100nF" CC1005-0402 675,-1637.5 r180 top
C87 "100nF" CC1005-0402 675,-1587.5 r180 top
C88 "100nF" CC1005-0402 675,-1437.5 r180 top
C89 "1.0uF" CC1608-0603 675,-1237.5 r90 top
C90 "10uF" CC2013-0805 700,-950 r90 top
C91 "4.7uF" CC1608-0603 728.35,-728.35 r90 top
C92 "4.7uF" CC1608-0603 728.35,728.35 r90 top
C93 "1.0uF" CC1005-0402 787.5,625 r180 top
C94 "100nF" CC1005-0402 792.32,-177.17 r0 top
C95 "100nF" CC1005-0402 792.32,162.5 r0 top
C96 "100pF" CC1005-0402 950,300 r90 top
C97 "1.0uF" CC1608-0603 1281.25,-1012.5 r0 top
C98 "6.8u Film" MKS2B046801M00 1418.75,637.5 r270 top
C99 "6.8u Film" MKS2B046801M00 1418.75,143.75 r90 top
C100 "1.0uF" CC1005-0402 1462.5,1350 r270 top
C101 "100nF" CC1005-0402 1512.5,1237.5 r0 top
C102 "100nF" CC1005-0402 1512.5,1462.5 r0 top
C103 "10uF" CC2013-0805 1550,1137.5 r270 top
C104 "10uF" CC2013-0805 1550,1562.5 r90 top
C105 "1.0uF" CC1608-0603 1575,-1312.36 r270 top
C106 "1.8nF" CC1005-0402 1600,1137.5 r270 top
C107 "1.8nF" CC1005-0402 1600,1562.5 r90 top
C108 "1.0uF" CC1005-0402 1687.5,1562.5 r90 top
C109 "1.0uF" CC1005-0402 1725,1562.5 r270 top
C110 "5.6nF" CC1005-0402 1850,1137.5 r270 top
C111 "2.7nF" CC1005-0402 1850,1562.5 r90 top
C112 "47uF" CC3216-1206 1912.5,1137.5 r90 top
C113 "47uF" CC3216-1206 1912.5,1562.5 r90 top
C114 "100nF" CC1005-0402 1912.5,1300 r270 top
C115 "100nF" CC1005-0402 1912.5,1400 r90 top
C116 "10uF" CC2013-0805 1700,556.25 r0 top
C117 "10uF" CC2013-0805 1700,206.25 r180 top
C118 "47nF" CC1005-0402 2618.75,-1225 r270 top
C119 "47nF" CC1005-0402 2618.75,-1075 r270 top
C120 "47nF" CC1005-0402 2618.75,62.5 r270 top
C121 "47nF" CC1005-0402 2618.75,212.5 r270 top
C122 "10uF" CC3225-1210 2718.75,-718.75 r0 top value=10uf
C123 "10uF" CC3225-1210 2718.75,-587.5 r180 top value=10uf
C124 "10uF" CC3225-1210 2718.75,-437.5 r180 top value=10uf
C125 "10uF" CC3225-1210 2718.75,-306.25 r0 top value=10uf
C126 "10uF" CC3225-1210 2718.75,575 r180 top value=10uf
C127 "10uF" CC3225-1210 2718.75,706.25 r0 top value=10uf
C128 "10uF" CC3225-1210 2743.75,-1562.5 r90 top value=10uf
C129 "100pF" CC1005-0402 2776.25,-1237.5 r180 top
C130 "100pF" CC1005-0402 2776.25,50 r180 top
C131 "100pF" CC1005-0402 2776.25,-1062.5 r0 top
C132 "100pF" CC1005-0402 2776.25,225 r0 top
C133 "2.2uF" CC3216-1206 2968.75,-1362.5 r180 top
C134 "2.2uF" CC3216-1206 2968.75,-937.5 r0 top
C135 "2.2uF" CC3216-1206 2968.75,-87.5 r0 top
C136 "2.2uF" CC3216-1206 2968.75,362.5 r0 top
C137 "1.0uF" CC1005-0402 3148.75,-1132.5 r180 top
C138 "100nF" CC1005-0402 3148.75,155 r180 top
C139 "1.0uF" CC1005-0402 3148.75,-1167.5 r0 top
C140 "100nF" CC1005-0402 3148.75,120 r0 top
C141 "10uF" CC3225-1210 3200,-1600 r270 top value=10uf
C142 "10uF" CC3225-1210 2718.75,-1150 r180 bottom value=10uf
C143 "10uF" CC3225-1210 2718.75,137.5 r180 bottom value=10uf
C144 "47uF" CC5650-2220 2487.5,-168.75 r0 bottom
C145 "47uF" CC5650-2220 2487.5,318.75 r180 bottom
C146 "100nF" CC1005-0402 2587.5,1375 r180 top
C147 "10uF" CC2013-0805 2589.07,1037.5 r90 bottom
C148 "47uF" CC3216-1206 2456.25,-812.5 r270 bottom
C149 "47uF" CC3216-1206 2456.25,-612.5 r270 bottom
C150 "10uF" CC3225-1210 2393.75,-1512.5 r0 bottom value=10uf
C151 "10uF" CC3225-1210 2393.75,-1012.5 r180 bottom value=10uf
C152 "100nF" CC1608-0603 2150,962.5 r270 top
C153 "1.0uF" CC1608-0603 2243.75,-812.5 r270 bottom
C154 "1.0uF" CC1608-0603 2243.75,-612.5 r270 bottom
C155 "100nF" CC1608-0603 2150,1687.5 r90 top
C156 "3.3uF Film" CC3225-1210 1937.52,-112.26 r90 bottom
C157 "3.3uF Film" CC3225-1210 1937.5,-1412.5 r90 bottom
C158 "3.3uF Film" CC3225-1210 1937.5,-1212.5 r90 bottom
C159 "3.3uF Film" CC3225-1210 1937.5,-712.5 r270 bottom
C160 "3.3uF Film" CC3225-1210 1937.5,-512.5 r270 bottom
C161 "3.3uF Film" CC3225-1210 1937.5,-312.5 r270 bottom
C162 "3.3uF Film" CC3225-1210 2162.5,243.75 r180 top
C163 "10uF" CC2013-0805 1925,1237.5 r270 bottom
C164 "10uF" CC2013-0805 1925,1462.5 r90 bottom
C165 "10uF" CC3225-1210 1737.5,-1412.5 r90 bottom value=10uf
C166 "10uF" CC3225-1210 1737.5,-1212.5 r90 bottom value=10uf
C167 "10uF" CC3225-1210 1700,-393.75 r180 bottom value=10uf
C168 "10uF" CC3225-1210 1700,-231.25 r180 bottom value=10uf
C169 "10uF" CC3225-1210 1700,-12.5 r180 bottom value=10uf
C170 "10uF" CC3225-1210 1937.5,387.5 r0 bottom value=10uf
C171 "10uF" CC3225-1210 1937.5,587.5 r0 bottom value=10uf
C172 "10uF" CC2013-0805 1675,-812.5 r180 bottom
C173 "10uF" CC2013-0805 1675,-612.5 r0 bottom
C174 "10uF" CC2013-0805 1487.5,1250 r180 bottom
C175 "10uF" CC2013-0805 1487.5,1450 r180 bottom
C176 "1.0uF" CC1005-0402 1507.5,1312.5 r0 bottom
C177 "100nF" CC1005-0402 1450,-1225 r0 bottom
C178 "100nF" CC1608-0603 1225,962.5 r180 top
C179 "100nF" CC1608-0603 1225,1412.5 r180 top
C180 "100nF" CC1005-0402 962.5,0 r90 bottom
C181 "1.0uF" CC1005-0402 937.5,-1175 r90 bottom
C182 "4.7uF" CC1608-0603 728.35,-728.35 r90 bottom
C183 "4.7uF" CC1608-0603 728.35,728.35 r90 bottom
C184 "100pF" CC1005-0402 725,550 r90 bottom
C185 "47uF" CC3216-1206 649.61,-728.35 r90 bottom
C186 "47uF" CC3216-1206 649.61,728.35 r90 bottom
C187 "NL" CC1005-0402 590.55,0 r90 bottom
C188 "10uF" CC2013-0805 537.5,-1325 r0 bottom
C189 "4.7uF" CC1608-0603 570.87,-787.4 r90 bottom
C190 "1.0uF" CC1608-0603 570.87,-669.29 r270 bottom
C191 "4.7uF" CC1608-0603 570.87,669.29 r90 bottom
C192 "4.7uF" CC1608-0603 570.87,787.4 r270 bottom
C193 "10uF" CC2013-0805 511.81,236.22 r180 bottom
C194 "10uF" CC2013-0805 511.81,503.94 r180 bottom
C195 "1.0uF" CC1608-0603 512.6,-1562.5 r180 bottom
C196 "100nF" CC1005-0402 538.19,-1270.69 r180 bottom
C197 "100nF" CC1005-0402 511.81,177.17 r180 bottom
C198 "1.0uF" CC1608-0603 512.5,-950 r270 bottom
C199 "4.7uF" CC1608-0603 511.81,669.29 r90 bottom
C200 "4.7uF" CC1608-0603 511.81,787.4 r270 bottom
C201 "4.7uF" CC1608-0603 452.76,669.29 r90 bottom
C202 "1.0uF" CC1608-0603 452.76,787.4 r270 bottom
C203 "100nF" CC1005-0402 433.07,59.06 r90 bottom
C204 "47uF" CC3216-1206 374.02,728.35 r270 bottom
C205 "470nF" FP-CL03-IPC_B 374.02,295.28 r135 bottom
C206 "470nF" FP-CL03-IPC_B 374.02,-118.11 r180 bottom
C207 "470nF" FP-CL03-IPC_B 374.02,78.74 r0 bottom
C208 "470nF" FP-CL03-IPC_B 334.65,-236.22 r0 bottom
C209 "470nF" FP-CL03-IPC_B 334.65,196.85 r0 bottom
C210 "470nF" FP-CL03-IPC_B 314.96,-334.65 r90 bottom
C211 "470nF" FP-CL03-IPC_B 275.59,-413.39 r90 bottom
C212 "100nF" CC1005-0402 275.59,216.54 r270 bottom
C213 "470nF" FP-CL03-IPC_B 236.22,-334.65 r270 bottom
C214 "470nF" FP-CL03-IPC_B 236.22,-177.17 r90 bottom
C215 "NL" CC2013-0805 162.5,-1475 r180 bottom
C216 "470nF" FP-CL03-IPC_B 196.85,-413.39 r270 bottom
C217 "100nF" CC1005-0402 200,-775 r270 bottom
C218 "470nF" FP-CL03-IPC_B 177.17,78.74 r180 bottom
C219 "470nF" FP-CL03-IPC_B 177.17,118.11 r0 bottom
C220 "470nF" FP-CL03-IPC_B 177.17,-196.85 r0 bottom
C221 "470nF" FP-CL03-IPC_B 177.17,-157.48 r0 bottom
C222 "470nF" FP-CL03-IPC_B 177.17,-118.11 r180 bottom
C223 "470nF" FP-CL03-IPC_B 177.17,-78.74 r0 bottom
C224 "470nF" FP-CL03-IPC_B 177.17,39.37 r0 bottom
C225 "470nF" FP-CL03-IPC_B 177.17,157.48 r180 bottom
C226 "470nF" FP-CL03-IPC_B 177.17,196.85 r0 bottom
C227 "470nF" FP-CL03-IPC_B 177.17,236.22 r0 bottom
C228 "470nF" FP-CL03-IPC_B 157.48,334.65 r90 bottom
C229 "470nF" FP-CL03-IPC_B 137.8,-314.96 r270 bottom
C230 "100nF" CC1005-0402 150,-912.5 r270 bottom
C231 "470nF" FP-CL03-IPC_B 118.11,-216.54 r90 bottom
C232 "10uF" CC2013-0805 112.5,-1050 r270 bottom
C233 "NL" FP-CL03-IPC_B 98.43,-19.68 r225 bottom
C234 "470nF" FP-CL03-IPC_B 98.43,-78.74 r180 bottom
C235 "470nF" FP-CL03-IPC_B 98.43,118.11 r180 bottom
C236 "470nF" FP-CL03-IPC_B 98.43,157.48 r180 bottom
C237 "470nF" FP-CL03-IPC_B 98.43,196.85 r0 bottom
C238 "470nF" FP-CL03-IPC_B 98.43,-393.7 r90 bottom
C239 "470nF" FP-CL03-IPC_B 78.74,-334.65 r90 bottom
C240 "470nF" FP-CL03-IPC_B 78.74,-216.54 r90 bottom
C241 "470nF" FP-CL03-IPC_B 78.74,374.02 r270 bottom
C242 "470nF" FP-CL03-IPC_B 59.06,-157.48 r180 bottom
C243 "470nF" FP-CL03-IPC_B 59.06,-118.11 r0 bottom
C244 "470nF" FP-CL03-IPC_B 59.06,78.74 r180 bottom
C245 "100nF" CC1005-0402 75,-912.5 r270 bottom
C246 "470nF" FP-CL03-IPC_B 39.37,-59.05 r270 bottom
C247 "470nF" FP-CL03-IPC_B 39.37,177.17 r270 bottom
C248 "NL" CC2013-0805 37.5,-1562.5 r90 bottom
C249 "100nF" CC1005-0402 -12.5,-775 r270 bottom
C250 "470nF" FP-CL03-IPC_B -39.37,-255.91 r90 bottom
C251 "470nF" FP-CL03-IPC_B -39.37,-177.17 r90 bottom
C252 "470nF" FP-CL03-IPC_B -39.37,137.8 r270 bottom
C253 "470nF" FP-CL03-IPC_B -39.37,374.02 r90 bottom
C254 "470nF" FP-CL03-IPC_B -59.06,-59.06 r315 bottom
C255 "470nF" FP-CL03-IPC_B -59.06,-118.11 r180 bottom
C256 "470nF" FP-CL03-IPC_B -78.74,-334.65 r270 bottom
C257 "100nF" CC1005-0402 -98.43,-275.72 r180 bottom
C258 "470nF" FP-CL03-IPC_B -98.43,118.11 r180 bottom
C259 "470nF" FP-CL03-IPC_B -118.11,374.02 r90 bottom
C260 "470nF" FP-CL03-IPC_B -137.8,39.37 r0 bottom
C261 "470nF" FP-CL03-IPC_B -157.48,-295.28 r90 bottom
C262 "470nF" FP-CL03-IPC_B -177.17,-39.37 r180 bottom
C263 "470nF" FP-CL03-IPC_B -196.85,216.88 r90 bottom
C264 "470nF" FP-CL03-IPC_B -216.54,-118.11 r0 bottom
C265 "470nF" FP-CL03-IPC_B -236.22,-255.91 r270 bottom
C266 "100nF" CC1005-0402 -295.28,-748.03 r180 bottom
C267 "10uF" CC2013-0805 -343.75,-1431.25 r180 bottom
C268 "100nF" CC1005-0402 -275.59,177.17 r90 bottom
C269 "470nF" FP-CL03-IPC_B -295.28,236.22 r180 bottom
C270 "470nF" FP-CL03-IPC_B -295.28,314.96 r180 bottom
C271 "470nF" FP-CL03-IPC_B -314.96,-216.54 r90 bottom
C272 "1.0nF COG" CC1005-0402 -343.75,-1368.75 r0 bottom
C273 "470nF" FP-CL03-IPC_B -413.39,196.85 r180 bottom
C274 "220nF" CC1005-0402 -550,-1350 r90 bottom
C275 "220nF" CC1005-0402 -587.5,-1350 r90 bottom
C276 "220nF" CC1005-0402 -637.5,-1350 r90 bottom
C277 "220nF" CC1005-0402 -675,-1350 r90 bottom
C278 "220nF" CC1005-0402 -725,-1350 r90 bottom
C279 "220nF" CC1005-0402 -762.5,-1350 r90 bottom
C280 "220nF" CC1005-0402 -812.5,-1350 r90 bottom
C281 "100nF" CC1005-0402 -812.5,-147.34 r270 bottom
C282 "220nF" CC1005-0402 -850,-1350 r90 bottom
C283 "10nF" CC1005-0402 -925.2,167.32 r0 bottom
C284 "10nF" CC1005-0402 -900,-1350 r90 bottom
C285 "10nF" CC1005-0402 -937.5,-1350 r90 bottom
C286 "100nF" CC1005-0402 -1137.5,-1350 r90 bottom
C287A "100nF" CC0603-0201 -1312.5,1470 r90 bottom locked (schematic designator C287)
C287B "100nF" CC0603-0201 -1312.5,570 r90 bottom locked (schematic designator C287)
C287C "100nF" CC0603-0201 -1312.5,-330 r90 bottom locked (schematic designator C287)
C287D "100nF" CC0603-0201 -1312.5,-1230 r90 bottom locked (schematic designator C287)
C291A "10uF" CC3225-1210 -1487.5,1537.5 r0 bottom locked value=10uf (schematic designator C291)
C291B "10uF" CC3225-1210 -1487.5,637.5 r0 bottom locked value=10uf (schematic designator C291)
C291C "10uF" CC3225-1210 -1487.5,-262.5 r0 bottom locked value=10uf (schematic designator C291)
C291D "10uF" CC3225-1210 -1487.5,-1162.5 r0 bottom locked value=10uf (schematic designator C291)
C295A "100nF" CC0603-0201 -1442.5,1455 r0 bottom locked (schematic designator C295)
C295B "100nF" CC0603-0201 -1442.5,555 r0 bottom locked (schematic designator C295)
C295C "100nF" CC0603-0201 -1442.5,-345 r0 bottom (schematic designator C295)
C295D "100nF" CC0603-0201 -1442.5,-1245 r0 bottom locked (schematic designator C295)
C299A "100nF" CC0603-0201 -1495,1182.5 r270 bottom locked (schematic designator C299)
C299B "100nF" CC0603-0201 -1495,282.5 r270 bottom locked (schematic designator C299)
C299C "100nF" CC0603-0201 -1495,-617.5 r270 bottom locked (schematic designator C299)
C299D "100nF" CC0603-0201 -1495,-1517.5 r270 bottom locked (schematic designator C299)
C303A "10uF" CC3225-1210 -1712.5,1537.5 r180 bottom locked value=10uf (schematic designator C303)
C303B "10uF" CC3225-1210 -1712.5,637.5 r180 bottom locked value=10uf (schematic designator C303)
C303C "10uF" CC3225-1210 -1712.5,-262.5 r180 bottom locked value=10uf (schematic designator C303)
C303D "10uF" CC3225-1210 -1712.5,-1162.5 r180 bottom locked value=10uf (schematic designator C303)
C307A "100nF" CC0603-0201 -1705,1182.5 r270 bottom locked (schematic designator C307)
C307B "100nF" CC0603-0201 -1705,282.5 r270 bottom locked (schematic designator C307)
C307C "100nF" CC0603-0201 -1705,-617.5 r270 bottom locked (schematic designator C307)
C307D "100nF" CC0603-0201 -1705,-1517.5 r270 bottom locked (schematic designator C307)
C311A "200pF" CC1005-0402 -1887.5,962.5 r225 bottom locked (schematic designator C311)
C311B "200pF" CC1005-0402 -1887.5,62.5 r225 bottom locked (schematic designator C311)
C311C "200pF" CC1005-0402 -1887.5,-837.5 r225 bottom locked (schematic designator C311)
C311D "200pF" CC1005-0402 -1887.5,-1737.5 r225 bottom locked (schematic designator C311)
C315A "200pF" CC1005-0402 -1987.5,1062.5 r225 bottom locked (schematic designator C315)
C315B "200pF" CC1005-0402 -1987.5,162.5 r225 bottom locked (schematic designator C315)
C315C "200pF" CC1005-0402 -1987.5,-737.5 r225 bottom locked (schematic designator C315)
C315D "200pF" CC1005-0402 -1987.5,-1637.5 r225 bottom locked (schematic designator C315)
C319A "2.2nF" CC1608-0603 -2150,1237.5 r270 bottom locked (schematic designator C319)
C319B "2.2nF" CC1608-0603 -2150,1462.5 r270 bottom locked (schematic designator C319)
C319C "2.2nF" CC1608-0603 -2150,1687.5 r270 bottom locked (schematic designator C319)
C319D "2.2nF" CC1608-0603 -2150,1012.5 r270 bottom locked (schematic designator C319)
C319E "2.2nF" CC1608-0603 -2150,337.5 r270 bottom locked (schematic designator C319)
C319F "2.2nF" CC1608-0603 -2150,562.5 r270 bottom locked (schematic designator C319)
C319G "2.2nF" CC1608-0603 -2150,787.5 r270 bottom locked (schematic designator C319)
C319H "2.2nF" CC1608-0603 -2150,112.5 r270 bottom locked (schematic designator C319)
C319I "2.2nF" CC1608-0603 -2150,-562.5 r270 bottom locked (schematic designator C319)
C319J "2.2nF" CC1608-0603 -2150,-337.5 r270 bottom locked (schematic designator C319)
C319K "2.2nF" CC1608-0603 -2150,-112.5 r270 bottom locked (schematic designator C319)
C319L "2.2nF" CC1608-0603 -2150,-787.5 r270 bottom locked (schematic designator C319)
C319M "2.2nF" CC1608-0603 -2150,-1462.5 r270 bottom locked (schematic designator C319)
C319N "2.2nF" CC1608-0603 -2150,-1237.5 r270 bottom locked (schematic designator C319)
C319O "2.2nF" CC1608-0603 -2150,-1012.5 r270 bottom locked (schematic designator C319)
C319P "2.2nF" CC1608-0603 -2150,-1687.5 r270 bottom locked (schematic designator C319)
C335A "100nF" CC1005-0402 -2175,1312.5 r180 bottom locked (schematic designator C335)
C335B "100nF" CC1005-0402 -2175,1537.5 r180 bottom locked (schematic designator C335)
C335C "100nF" CC1005-0402 -2175,1762.5 r180 bottom locked (schematic designator C335)
C335D "100nF" CC1005-0402 -2175,1087.5 r180 bottom locked (schematic designator C335)
C335E "100nF" CC1005-0402 -2175,412.5 r180 bottom locked (schematic designator C335)
C335F "100nF" CC1005-0402 -2175,637.5 r180 bottom locked (schematic designator C335)
C335G "100nF" CC1005-0402 -2175,862.5 r180 bottom locked (schematic designator C335)
C335H "100nF" CC1005-0402 -2175,187.5 r180 bottom locked (schematic designator C335)
C335I "100nF" CC1005-0402 -2175,-487.5 r180 bottom locked (schematic designator C335)
C335J "100nF" CC1005-0402 -2175,-262.5 r180 bottom locked (schematic designator C335)
C335K "100nF" CC1005-0402 -2175,-37.5 r180 bottom locked (schematic designator C335)
C335L "100nF" CC1005-0402 -2175,-712.5 r180 bottom locked (schematic designator C335)
C335M "100nF" CC1005-0402 -2175,-1387.5 r180 bottom locked (schematic designator C335)
C335N "100nF" CC1005-0402 -2175,-1162.5 r180 bottom locked (schematic designator C335)
C335O "100nF" CC1005-0402 -2175,-937.5 r180 bottom locked (schematic designator C335)
C335P "100nF" CC1005-0402 -2175,-1612.5 r180 bottom locked (schematic designator C335)
C351A "NL" CC1005-0402 -2300,1212.5 r270 bottom locked (schematic designator C351)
